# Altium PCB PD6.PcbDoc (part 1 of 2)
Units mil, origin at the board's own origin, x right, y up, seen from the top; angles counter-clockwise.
Board outline 8543.31 x 5314.96 mil, 4 copper layers (Top Layer, VBAT Plane, GND Plane, Bottom Layer), stack 62.8 mil thick; 258 components, 142 nets, 690 pads, 87 vias.
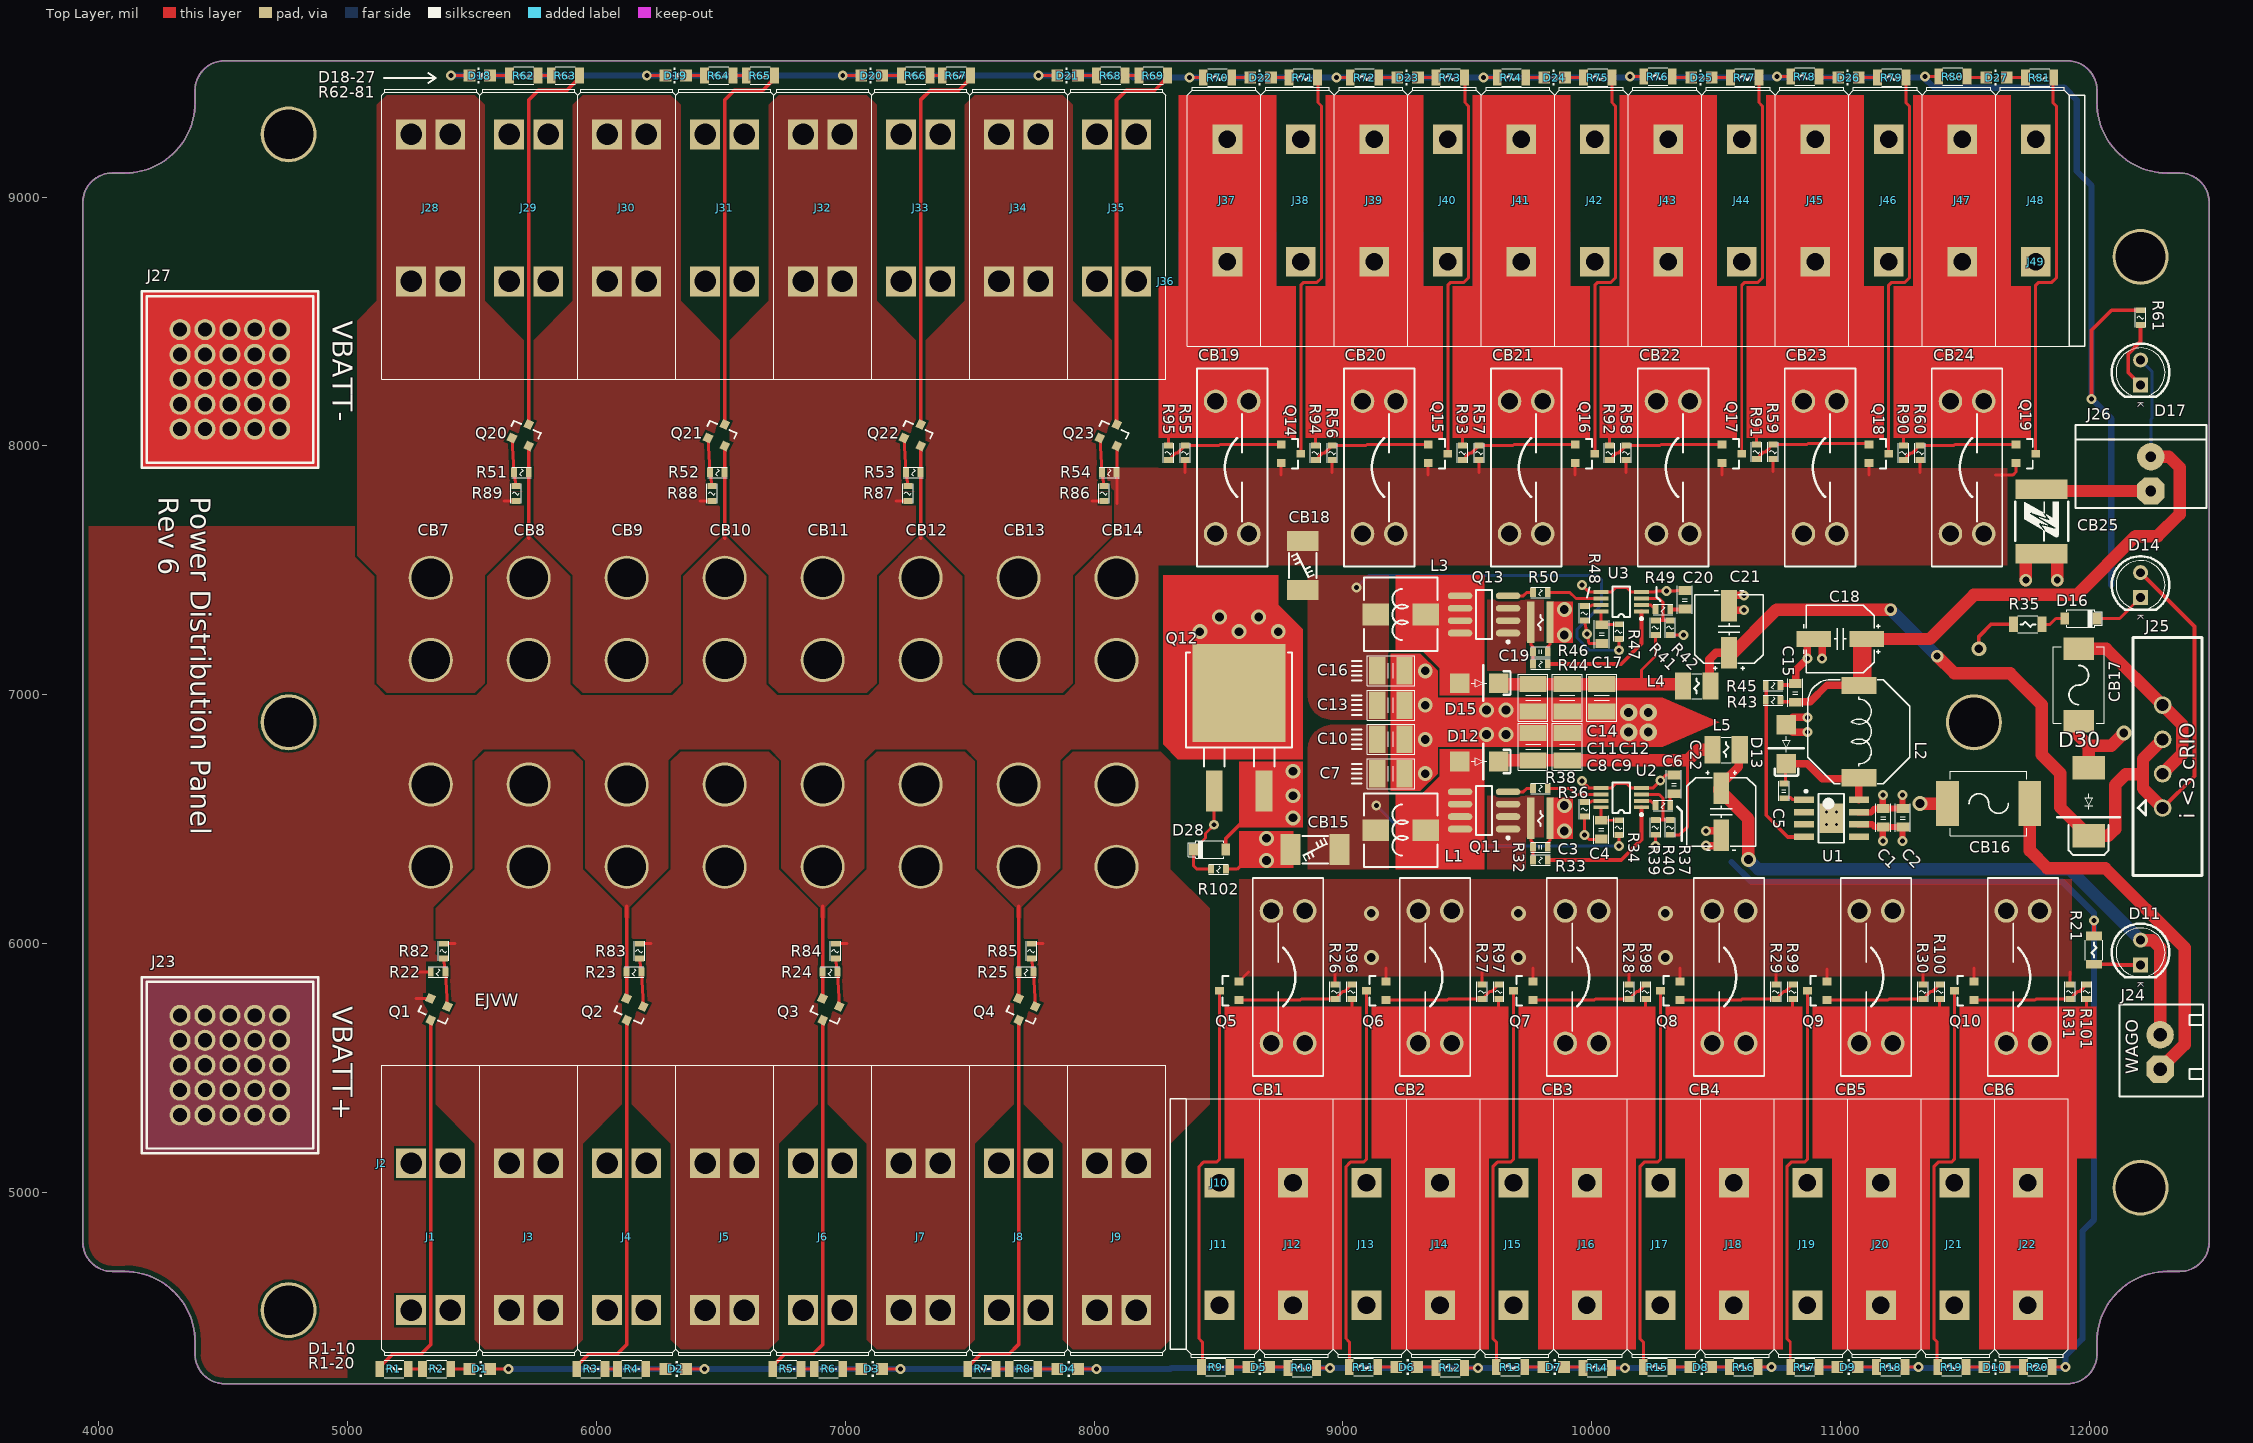
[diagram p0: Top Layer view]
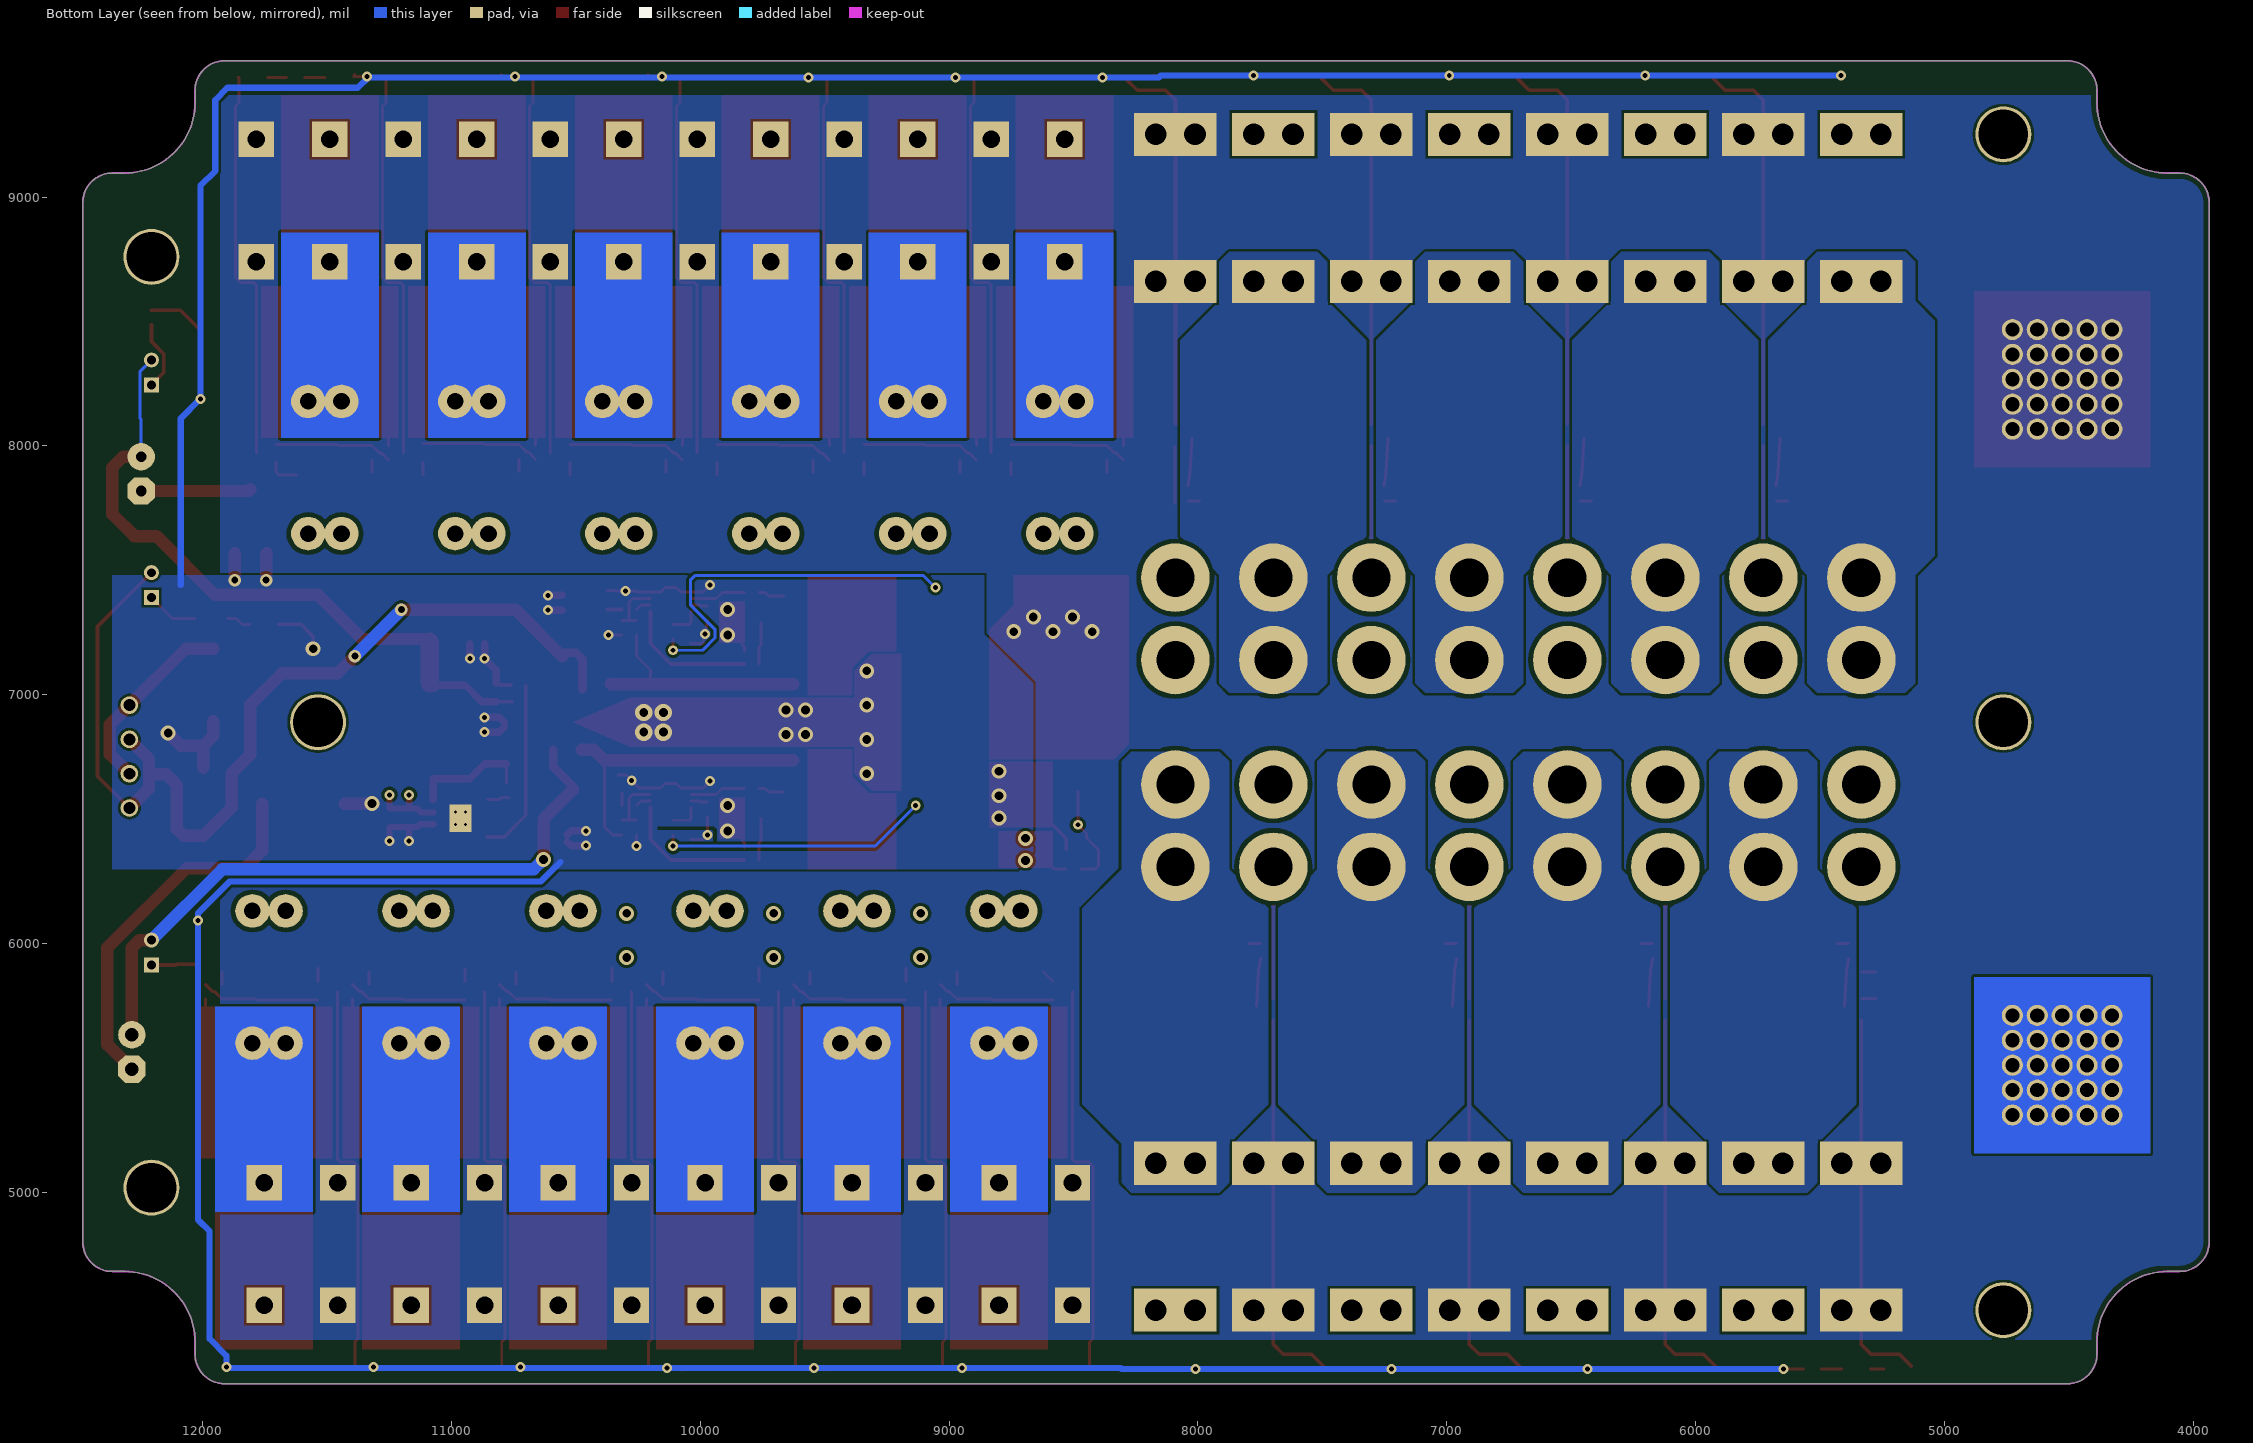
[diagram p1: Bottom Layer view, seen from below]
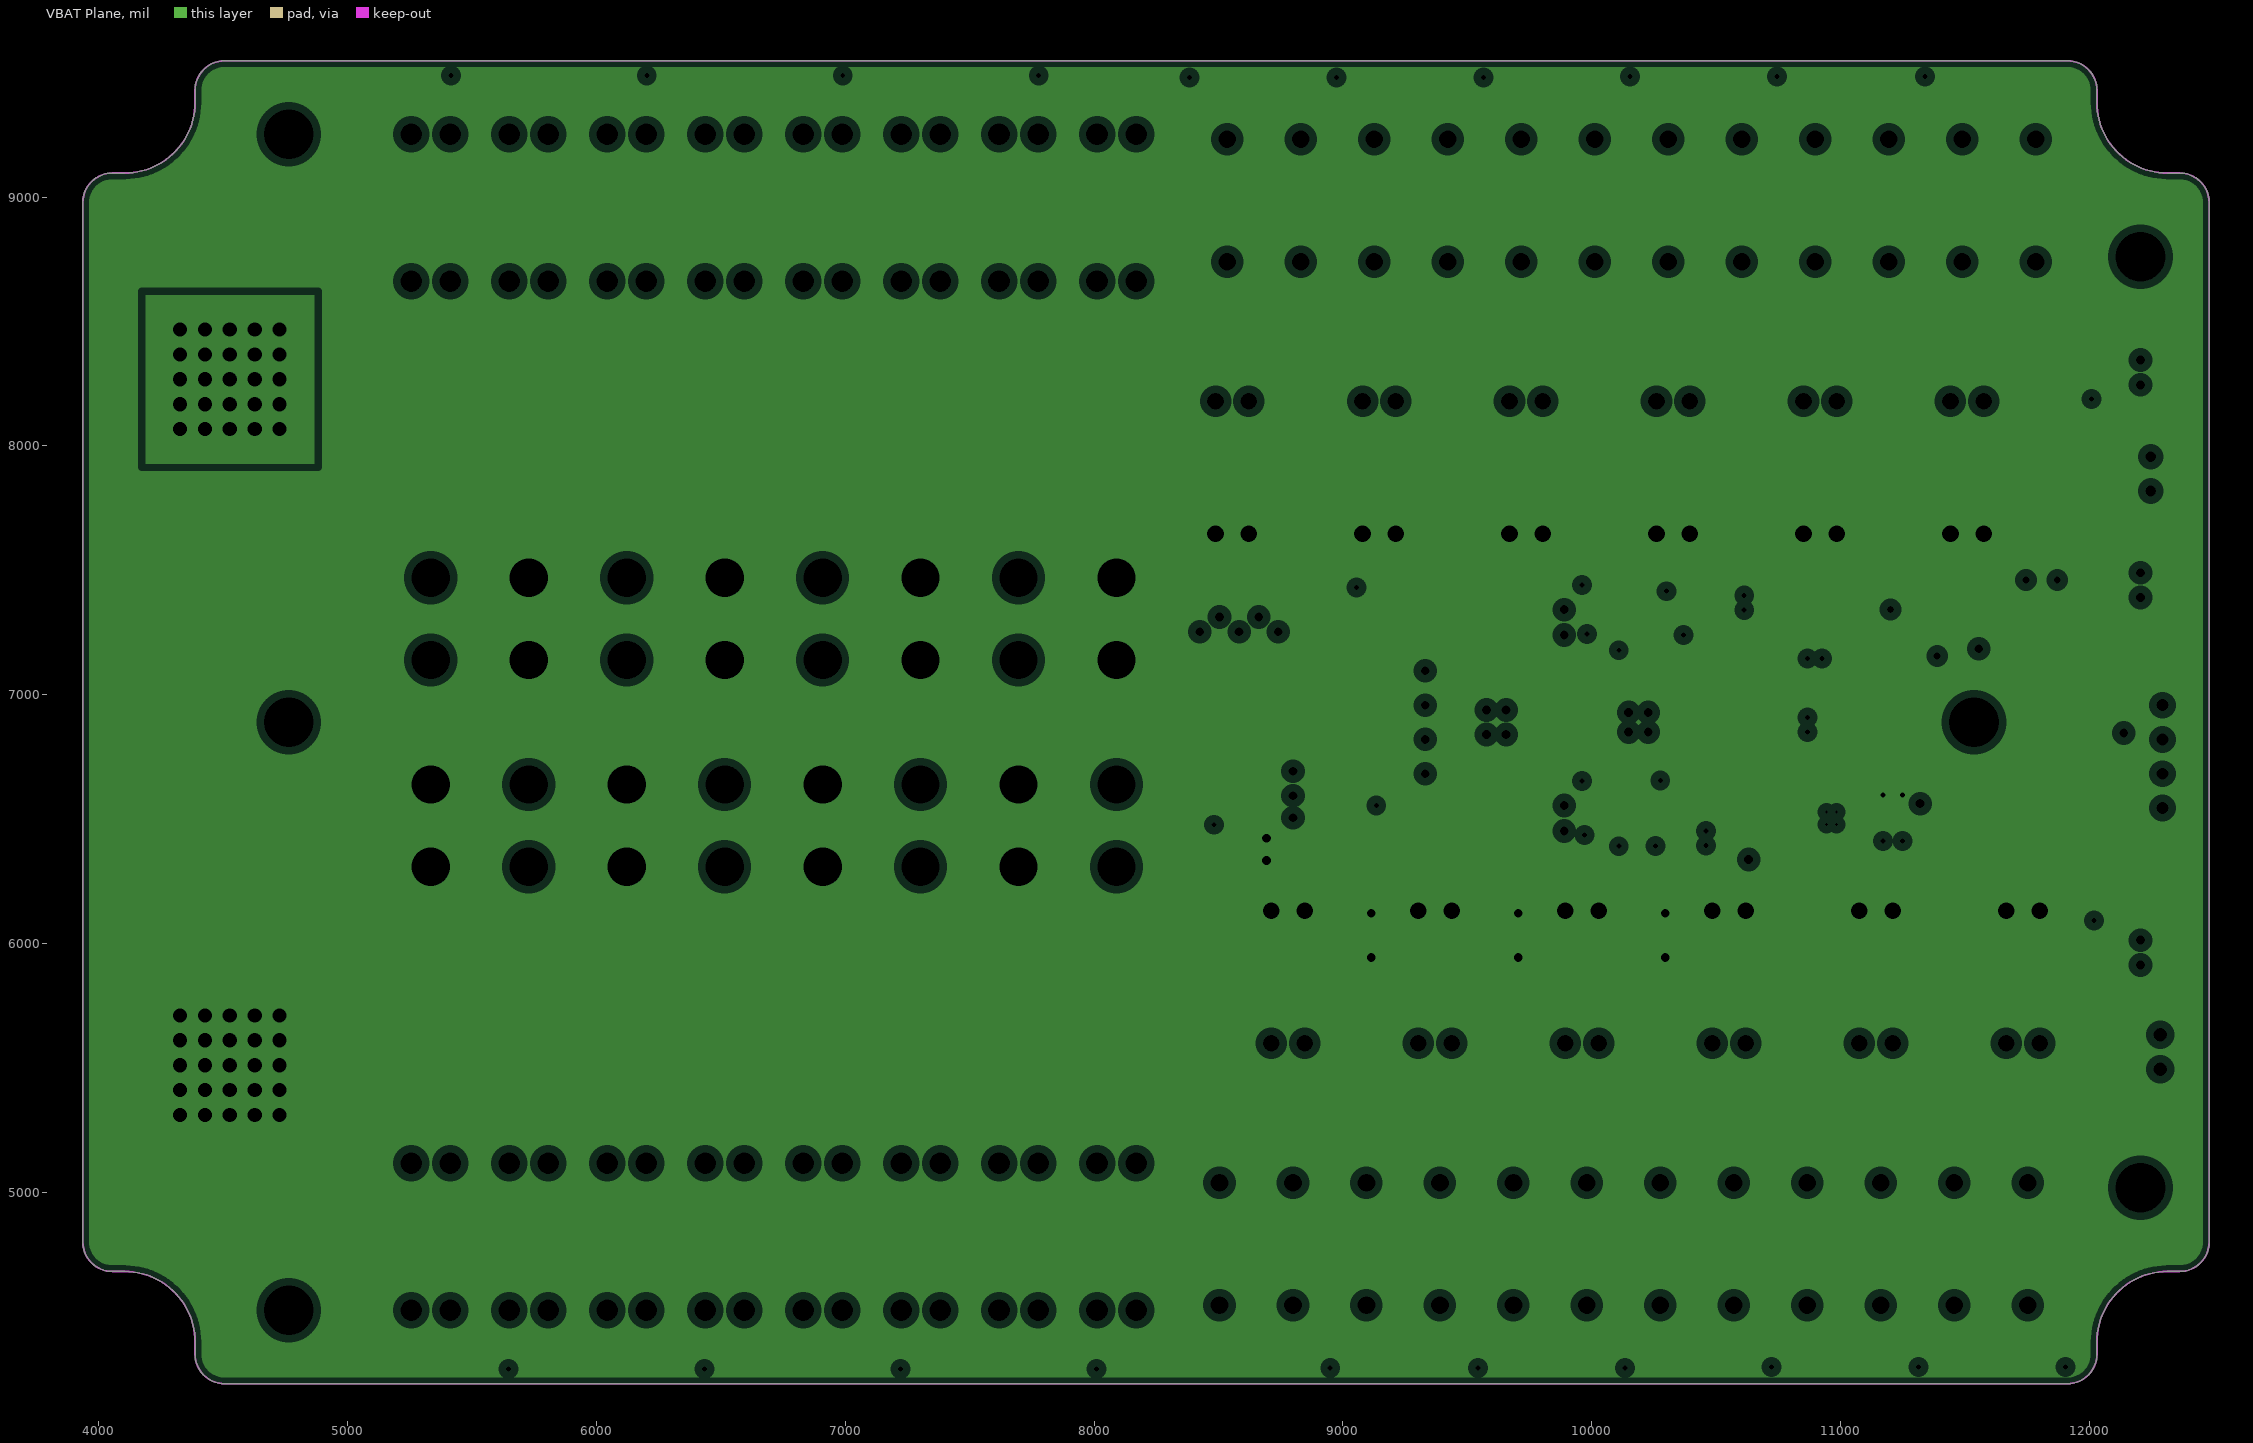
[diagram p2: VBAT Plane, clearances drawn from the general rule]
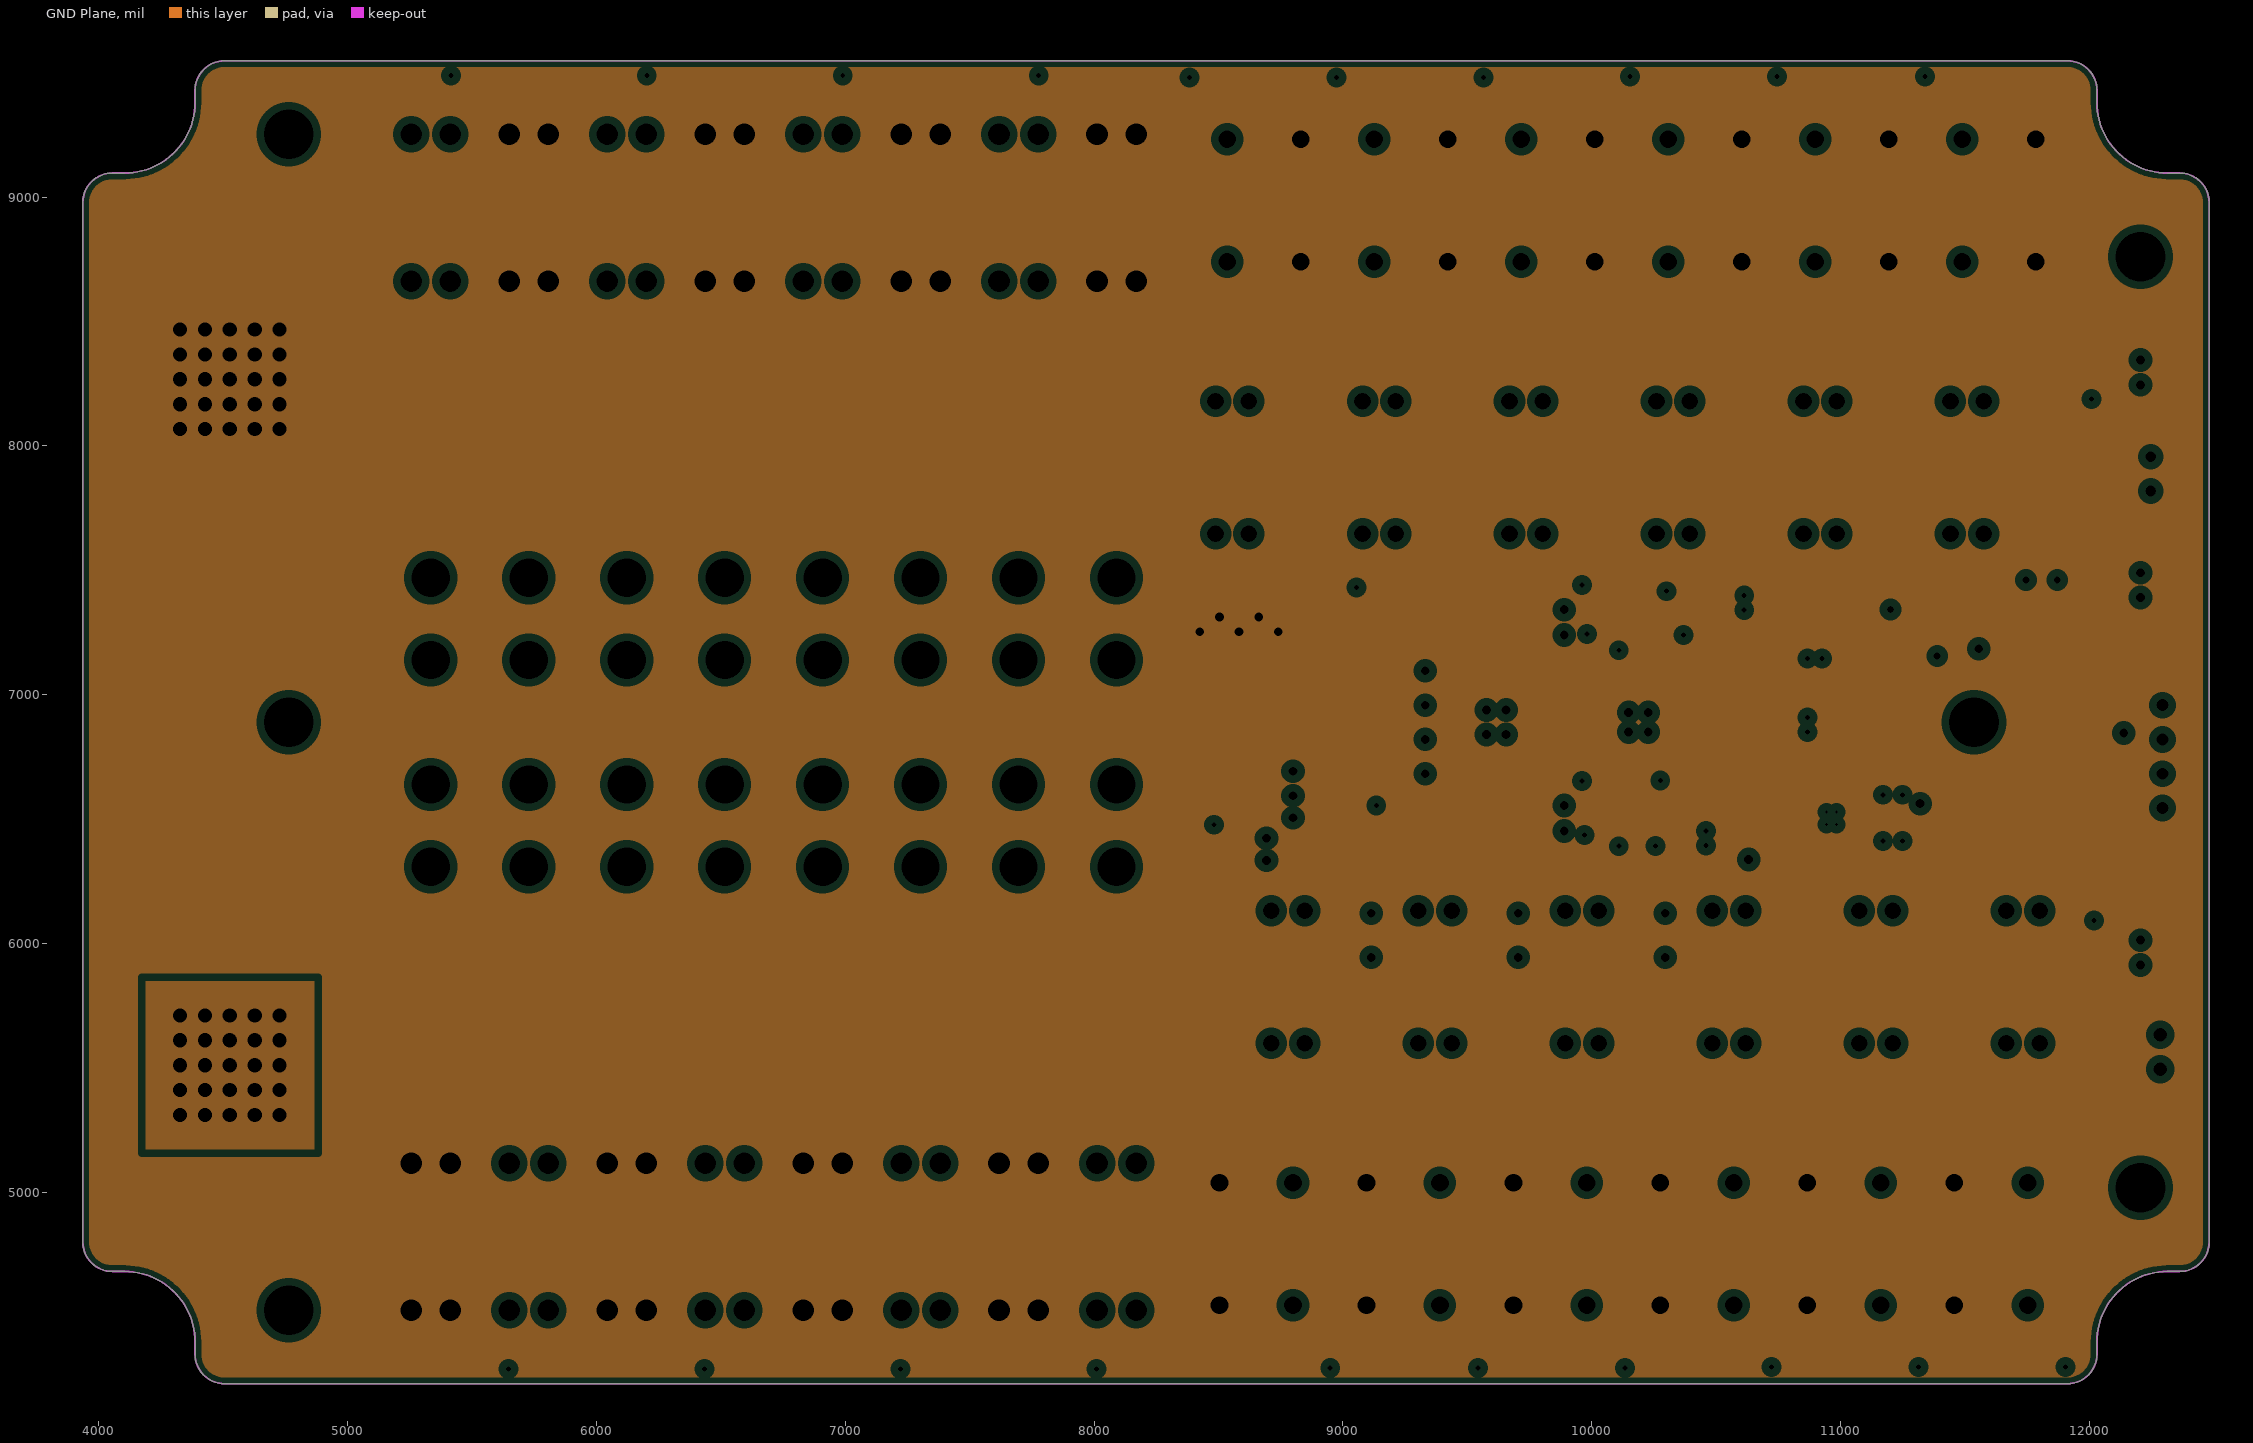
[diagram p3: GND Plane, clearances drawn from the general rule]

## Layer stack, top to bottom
Top Layer: signal copper 2.4
Dielectric: prepreg 10, FR-4, Dk 4.8
VBAT Plane: plane copper 5, net (Multiple Nets)
Dielectric: core 28, FR-4, Dk 4.8
GND Plane: plane copper 5, net (Multiple Nets)
Dielectric: prepreg 10, FR-4, Dk 4.8
Bottom Layer: signal copper 2.4

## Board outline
4055.12,4683.07 4104.33,4683.07 cw(c4104.33,4399.61) 4387.8,4399.61 4387.8,4350.39 ccw(c4505.91,4350.39) 4505.91,4232.28 11911.42,4232.28 ccw(c11911.42,4350.39) 12029.53,4350.39 12029.53,4399.61 cw(c12312.99,4399.61) 12312.99,4683.07 12362.2,4683.07 ccw(c12362.2,4801.18) 12480.31,4801.18 12480.31,8978.35 ccw(c12362.2,8978.35) 12362.2,9096.46 12312.99,9096.46 cw(c12312.99,9379.92) 12029.53,9379.92 12029.53,9429.13 ccw(c11911.42,9429.13) 11911.42,9547.24 4505.91,9547.24 ccw(c4505.91,9429.13) 4387.8,9429.13 4387.8,9379.92 cw(c4104.33,9379.92) 4104.33,9096.46 4055.12,9096.46 ccw(c4055.12,8978.35) 3937.01,8978.35 3937.01,4801.18 ccw(c4055.12,4801.18)

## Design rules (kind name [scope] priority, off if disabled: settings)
Clearance "CLR Inner Planes" [OnLayer('GND Plane') or OnLayer('VBAT Plane')] p1: gap=30
Clearance Clearance_Breakers [(HasFootprint('KEYSTONE 3555-2') OR HasFootprint('KEYSTONE 3557-2'))] p2: gap=18
Clearance CLR_Board_Edge [(InPolygon) vs OnLayer('Keep-Out Layer')] p3: gap=20
Clearance Clearance_PolyPoly [(InPolygon) vs (InPolygon or IsPad or IsFill)] p4: gap=10
Clearance CLR_Poly [(InPolygon)] p5: gap=12
Clearance [All] p6: gap=9.02
ComponentClearance "CC Wago236" [(HasFootprint('WAGO 236-74X') OR HasFootprint('WAGO 236-75X'))] p1 off: gap=-39.37 collisioncheckmode=3 verticalgap=0 showdistances=FALSE
ComponentClearance "ComponentClearance_WAGO Small" [(HasFootprint('WAGO 745-83X') OR HasFootprint('WAGO 745-83X Red') OR HasFootprint('WAGO 745-300')) vs (HasFootprint('WAGO 745-83X') OR HasFootprint('WAGO 745-83X Red') OR HasFootprint('WAGO 745-300'))] p2 off: gap=-3937.01 collisioncheckmode=3 verticalgap=0 showdistances=FALSE
ComponentClearance ComponentClearance_WAGOs [(HasFootprint('WAGO 745-85X') OR HasFootprint('WAGO 745-85X Red') OR HasFootprint('WAGO 745-500')) vs (HasFootprint('WAGO 745-85X') OR HasFootprint('WAGO 745-85X Red') OR HasFootprint('WAGO 745-500'))] p3 off: gap=-7874.02 collisioncheckmode=3 verticalgap=0 showdistances=FALSE
ComponentClearance [All] p4 off: gap=10 collisioncheckmode=3 verticalgap=10 showdistances=FALSE
Height Height_Bottom [OnLayer('Bottom Layer')] p1: minheight=0 maxheight=137.8 prefheight=39.37
Height [All] p2: minheight=0 maxheight=2500 prefheight=500
HoleSize [All] p1: absolutevalues=TRUE maxlimit=500 minlimit=10 maxpercent=80.000 minpercent=20.000
MinimumAnnularRing [All] p1: minimumring=10
PlaneClearance [All] p1: clearance=30
PlaneConnect PC_PowerSO8 [(HasFootprint('TPS543X'))] p1: planeconnectstyle=Direct reliefexpansion=20 reliefentries=4 reliefconductorwidth=10 reliefairgap=10
PlaneConnect PC_Wurth [(HasFootprint('WURTH 7460719'))] p2: planeconnectstyle=Direct reliefexpansion=20 reliefentries=4 reliefconductorwidth=10 reliefairgap=10
PlaneConnect "PC Wagos" [(HasFootprint('WAGO 745-83X') OR HasFootprint('WAGO 745-85X'))] p3: planeconnectstyle=Direct reliefexpansion=20 reliefentries=4 reliefconductorwidth=40 reliefairgap=25
PlaneConnect PC_Breakers [(HasFootprint('KEYSTONE 3555-2') OR HasFootprint('KEYSTONE 3557-2'))] p4: planeconnectstyle=Direct reliefexpansion=20 reliefentries=4 reliefconductorwidth=60 reliefairgap=20
PlaneConnect PC_Honkin [(InComponent('J1') OR InComponent('J2'))] p5: planeconnectstyle=Direct reliefexpansion=20 reliefentries=2 reliefconductorwidth=10 reliefairgap=10
PlaneConnect PC_Vias [IsVia] p6: planeconnectstyle=Direct reliefexpansion=20 reliefentries=4 reliefconductorwidth=10 reliefairgap=10
PlaneConnect [All] p7: planeconnectstyle=Direct reliefexpansion=30 reliefentries=4 reliefconductorwidth=30 reliefairgap=20
PolygonConnect "PGC Wago" [(HasFootprint('WAGO 745-83X') OR HasFootprint('WAGO 745-85X'))] p1: connectstyle=Direct reliefconductorwidth=45 reliefentries=4 polygonreliefangle="90 Angle"
PolygonConnect PGC_Breakers [HasFootprint('KEYSTONE 3555-2') OR HasFootprint('KEYSTONE 3557-2')] p2: connectstyle=Direct reliefconductorwidth=50 reliefentries=4 polygonreliefangle="45 Angle"
PolygonConnect PGC_Vias [(IsVia)] p3: connectstyle=Direct reliefconductorwidth=10 reliefentries=4 polygonreliefangle="90 Angle"
PolygonConnect PGC_VBAT_HP [All vs IsNamedPolygon('Top Layer-VBAT HP') or IsNamedPolygon('Bottom Layer-GND HP')] p4: connectstyle=Direct reliefconductorwidth=10 reliefentries=4 polygonreliefangle="45 Angle"
PolygonConnect [All] p5: connectstyle=Direct reliefconductorwidth=10 reliefentries=4 polygonreliefangle="90 Angle"
RoomDefinition "U_12V_2A Supply" [InComponentClass('U_12V_2A Supply')] p1: confinementstyle=ConfineIn formatcopy=TRUE lockcomponents=FALSE outline 8858.27,6299.21 10816.93,6299.21 10816.93,6889.76 8858.27,6889.76
RoomDefinition LPB2 [InComponentClass('LPB2')] p2: confinementstyle=ConfineIn formatcopy=TRUE lockcomponents=FALSE outline 8062.99,6889.76 12000,6889.76 12000,9645.67 8062.99,9645.67
RoomDefinition HPB1 [InComponentClass('HPB1')] p3: confinementstyle=ConfineIn formatcopy=TRUE lockcomponents=FALSE outline 8385.83,7677.17 5039.37,7677.17 5039.37,4133.86 8385.83,4133.86
RoomDefinition LPB1 [InComponentClass('LPB1')] p4: confinementstyle=ConfineIn formatcopy=TRUE lockcomponents=FALSE outline 12224.41,6889.76 8287.4,6889.76 8287.4,4133.86 12224.41,4133.86
RoomDefinition U1000 [InComponentClass('U1000')] p5: confinementstyle=ConfineIn formatcopy=TRUE lockcomponents=FALSE outline 8858.27,6889.76 10816.93,6889.76 10816.93,7480.31 8858.27,7480.31
RoomDefinition "U_5V_3A Supply" [InComponentClass('U_5V_3A Supply')] p6: confinementstyle=ConfineIn formatcopy=TRUE lockcomponents=FALSE outline 11299.21,6377.95 11299.21,7381.89 10669.29,7381.89 10669.29,6377.95
RoomDefinition HPB2 [InComponentClass('HPB2')] p7: confinementstyle=ConfineIn formatcopy=TRUE lockcomponents=FALSE outline 5039.37,6102.36 8385.83,6102.36 8385.83,9645.67 5039.37,9645.67
RoutingVias [All] p1: holewidth=30 width=50 viastyle="Through Hole" minholewidth=10 minwidth=30 maxholewidth=225 maxwidth=250
SolderMaskExpansion [All] p1: expansion=4
TestPointUsage [All] p1: valid=0 allowmultiple=FALSE
Testpoint [All] p1: side=15 testpointundercomponent=TRUE minsize=40 maxsize=100 preferedsize=60 minholesize=0 maxholesize=40 preferedholesize=32 testpointgrid=1 style=1021 order=0-112345678
Width Width_InnerPlanes [OnLayer('GND Plane') or OnLayer('VBAT Plane')] p1: maxlimit=100 minlimit=25 preferedwidth=30
Width [All] p2: maxlimit=500 minlimit=10 preferedwidth=12
14 further rules are at their usual default settings.

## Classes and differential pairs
component class "U_12V_2A Supply": C3 C4 C6 C7 C8 C9 C10 C22 D12 L1 L5 Q11 R32 R33 R34 R36 R37 R38 R39 R40 U2
component class "U_5V_3A Supply": C1 C2 C5 C15 C18 D13 L2 R43 R45 U1
component class PS1: CB15 CB16 CB17 CB18 CB25 D11 D14 D16 D17 D28 D30 J23 J24 J25 J26 J27 Q12 R21 R35 R61 R102
component class LPB2: CB19 CB20 CB21 CB22 CB23 CB24 D22 D23 D24 D25 D26 D27 J37 J38 J39 J40 J41 J42 J43 J44 J45 J46 J47 J48 J49 Q14 Q15 Q16 Q17 Q18 Q19 R55 R56 R57 R58 R59 R60 R70 R71 R72 R73 R74 R75 R76 R77 R78 R79 R80 R81 R90 R91 R92 R93 R94 R95
component class LPB1: CB1 CB2 CB3 CB4 CB5 CB6 D5 D6 D7 D8 D9 D10 J10 J11 J12 J13 J14 J15 J16 J17 J18 J19 J20 J21 J22 J50 Q5 Q6 Q7 Q8 Q9 Q10 R9 R10 R11 R12 R13 R14 R15 R16 R17 R18 R19 R20 R26 R27 R28 R29 R30 R31 R96 R97 R98 R99 R100 R101
component class HPB1: CB8 CB10 CB12 CB14 D1 D2 D3 D4 J1 J2 J3 J4 J5 J6 J7 J8 J9 Q1 Q2 Q3 Q4 R1 R2 R3 R4 R5 R6 R7 R8 R22 R23 R24 R25 R82 R83 R84 R85
channel class "PD - Low Power Bank": LPB1 LPB2
channel class "PD - High Power Bank": HPB1 HPB2
component class HPB2: CB7 CB9 CB11 CB13 D18 D19 D20 D21 J28 J29 J30 J31 J32 J33 J34 J35 J36 Q20 Q21 Q22 Q23 R51 R52 R53 R54 R62 R63 R64 R65 R66 R67 R68 R69 R86 R87 R88 R89
component class U1000: C11 C12 C13 C14 C16 C17 C19 C20 C21 D15 L3 L4 Q13 R41 R42 R44 R46 R47 R48 R49 R50 U3

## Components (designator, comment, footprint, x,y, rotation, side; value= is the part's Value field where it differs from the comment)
C1 "4.7UF 0805 25V X5R" C0805_C 11171.26,6505.91 r90 top (schematic designator C8)
C2 "4.7UF 0805 25V X5R" C0805_C 11250,6505.91 r90 top (schematic designator C9)
C3 "0.01uF 0603" C0603_C 9793.31,6387.8 r180 top (schematic designator C15)
C4 "0.1uF 0805 Bypass" C0805_C 10037.4,6458.66 r90 top (schematic designator C13)
C5 "0.01uF 0603" C0603_C 10771.65,6614.17 r90 top (schematic designator C10)
C6 "0.1uF 0805 Bypass" C0805_C 10330,6640 r270 top (schematic designator C14)
C7 "22uF 1210 High I_RMS" C1210_C 9192.91,6683.07 r180 top (schematic designator C16)
C8 "22uF 1210 High I_RMS" C1210_C 9763.78,6791.34 r270 top (schematic designator C18)
C9 "22uF 1210 High I_RMS" C1210_C 9901.57,6791.34 r270 top (schematic designator C17)
C10 "22uF 1210 High I_RMS" C1210_C 9192.91,6820.87 r180 top (schematic designator C19)
C11 "4.7uF 1210 High I_RMS" C1210_C 9901.57,6988.19 r90 top (schematic designator C6)
C12 "4.7uF 1210 High I_RMS" C1210_C 10039.37,6988.19 r90 top (schematic designator C5)
C13 "22uF 1210 High I_RMS" C1210_C 9192.91,6958.66 r180 top (schematic designator C4)
C14 "4.7uF 1210 High I_RMS" C1210_C 9763.78,6988.19 r90 top (schematic designator C7)
C15 "0.1uF 0805 Bypass" C0805_C 10816.93,7007.87 r270 top (schematic designator C11)
C16 "22uF 1210 High I_RMS" C1210_C 9192.91,7096.46 r180 top (schematic designator C20)
C17 "0.1uF 0805 Bypass" C0805_C 10039.37,7244.09 r90 top (schematic designator C1)
C18 "330µF SMT - Chemi-Con" "SMT-CAN NIPPON F80" 10998.03,7224.41 r270 top (schematic designator C12)
C19 "0.01uF 0603" C0603_C 9793.31,7173.23 r180 top (schematic designator C3)
C20 "0.1uF 0805 Bypass" C0805_C 10374.02,7381.89 r270 top (schematic designator C2)
C21 "100µF SMT - Panasonic" "SMT-CAN Panasonic D8" 10551.18,7263.78 r180 top
C22 "100µF SMT - Panasonic" "SMT-CAN Panasonic D8" 10520,6530 r0 top
CB1 "20/30 A Breaker Clip" "KEYSTONE 3557-2" 8779.53,5866.14 r270 top (schematic designator CB6)
CB2 "20/30 A Breaker Clip" "KEYSTONE 3557-2" 9370.08,5866.14 r270 top (schematic designator CB7)
CB3 "20/30 A Breaker Clip" "KEYSTONE 3557-2" 9960.63,5866.14 r270 top (schematic designator CB8)
CB4 "20/30 A Breaker Clip" "KEYSTONE 3557-2" 10551.18,5866.14 r270 top (schematic designator CB9)
CB5 "20/30 A Breaker Clip" "KEYSTONE 3557-2" 11141.73,5866.14 r270 top (schematic designator CB10)
CB6 "20/30 A Breaker Clip" "KEYSTONE 3557-2" 11732.28,5866.14 r270 top (schematic designator CB11)
CB7 "40 A Breaker Clip" "KEYSTONE 3555-2" 5334.65,6889.76 r90 top (schematic designator CB5)
CB8 "40 A Breaker Clip" "KEYSTONE 3555-2" 5728.35,6889.76 r270 top (schematic designator CB2)
CB9 "40 A Breaker Clip" "KEYSTONE 3555-2" 6122.05,6889.76 r90 top (schematic designator CB4)
CB10 "40 A Breaker Clip" "KEYSTONE 3555-2" 6515.75,6889.76 r270 top (schematic designator CB3)
CB11 "40 A Breaker Clip" "KEYSTONE 3555-2" 6909.45,6889.76 r90 top (schematic designator CB3)
CB12 "40 A Breaker Clip" "KEYSTONE 3555-2" 7303.15,6889.76 r270 top (schematic designator CB4)
CB13 "40 A Breaker Clip" "KEYSTONE 3555-2" 7696.85,6889.76 r90 top (schematic designator CB2)
CB14 "40 A Breaker Clip" "KEYSTONE 3555-2" 8090.55,6889.76 r270 top (schematic designator CB5)
CB15 "15A 125V" "FUSE2410 - BEL" 8887.8,6377.95 r180 top (schematic designator CB14)
CB16 "2 A Hold, 4 A Trip" PTC-MF-SM-Large 11594.49,6562.99 r0 top (schematic designator CB13)
CB17 "1.1 A Hold, 2.2 A Trip" PTC-MF-SM-Small 11956.69,7039.37 r90 top (schematic designator CB12)
CB18 "15A 125V" "FUSE2410 - BEL" 8838.58,7519.69 r90 top (schematic designator CB1)
CB19 "20/30 A Breaker Clip" "KEYSTONE 3557-2" 8555.12,7913.39 r90 top (schematic designator CB11)
CB20 "20/30 A Breaker Clip" "KEYSTONE 3557-2" 9145.67,7913.39 r90 top (schematic designator CB10)
CB21 "20/30 A Breaker Clip" "KEYSTONE 3557-2" 9736.22,7913.39 r90 top (schematic designator CB9)
CB22 "20/30 A Breaker Clip" "KEYSTONE 3557-2" 10326.77,7913.39 r90 top (schematic designator CB8)
CB23 "20/30 A Breaker Clip" "KEYSTONE 3557-2" 10917.32,7913.39 r90 top (schematic designator CB7)
CB24 "20/30 A Breaker Clip" "KEYSTONE 3557-2" 11507.87,7913.39 r90 top (schematic designator CB6)
CB25 "3 A Hold, 5 A Trip" 2920L 11807.09,7696.85 r90 top (schematic designator CB15)
D1 "Red 0805 2.0V 20mA 104mCd" "LED_0805 0.8 Red" 5531.5,4291.34 r0 top (schematic designator D2)
D2 "Red 0805 2.0V 20mA 104mCd" "LED_0805 0.8 Red" 6318.9,4291.34 r0 top (schematic designator D3)
D3 "Red 0805 2.0V 20mA 104mCd" "LED_0805 0.8 Red" 7106.3,4291.34 r0 top (schematic designator D4)
D4 "Red 0805 2.0V 20mA 104mCd" "LED_0805 0.8 Red" 7893.7,4291.34 r0 top (schematic designator D5)
D5 "Red 0805 2.0V 20mA 104mCd" "LED_0805 0.8 Red" 8661.42,4299.21 r0 top (schematic designator D6)
D6 "Red 0805 2.0V 20mA 104mCd" "LED_0805 0.8 Red" 9255.91,4299.21 r0 top (schematic designator D7)
D7 "Red 0805 2.0V 20mA 104mCd" "LED_0805 0.8 Red" 9846.46,4299.21 r0 top (schematic designator D8)
D8 "Red 0805 2.0V 20mA 104mCd" "LED_0805 0.8 Red" 10437.01,4299.21 r0 top (schematic designator D9)
D9 "Red 0805 2.0V 20mA 104mCd" "LED_0805 0.8 Red" 11027.56,4299.21 r0 top (schematic designator D10)
D10 "Red 0805 2.0V 20mA 104mCd" "LED_0805 0.8 Red" 11618.11,4299.21 r0 top (schematic designator D11)
D11 "Green" "T-1 3/4" 12204.72,5964.57 r270 top (schematic designator D17)
D12 "MBRA340T3G" SMA 9547.24,6732.28 r0 top (schematic designator D16)
D13 "MBRA340T3G" SMA 10781.5,6801.18 r270 top (schematic designator D12)
D14 "Green" "T-1 3/4" 12204.72,7440.94 r270 top
D15 "MBRA340T3G" SMA 9547.24,7047.24 r0 top (schematic designator D1)
D16 "MMSZ5242BT1G" SOD-123 11964.57,7307.09 r180 top (schematic designator D13)
D17 "Green" "T-1 3/4" 12204.72,8295.28 r270 top (schematic designator D15)
D18 "Red 0805 2.0V 20mA 104mCd" "LED_0805 0.8 Red" 5531.5,9488.19 r180 top (schematic designator D5)
D19 "Red 0805 2.0V 20mA 104mCd" "LED_0805 0.8 Red" 6318.9,9488.19 r180 top (schematic designator D4)
D20 "Red 0805 2.0V 20mA 104mCd" "LED_0805 0.8 Red" 7106.3,9488.19 r180 top (schematic designator D3)
D21 "Red 0805 2.0V 20mA 104mCd" "LED_0805 0.8 Red" 7893.7,9488.19 r180 top (schematic designator D2)
D22 "Red 0805 2.0V 20mA 104mCd" "LED_0805 0.8 Red" 8669.29,9480.32 r180 top (schematic designator D11)
D23 "Red 0805 2.0V 20mA 104mCd" "LED_0805 0.8 Red" 9259.84,9480.32 r180 top (schematic designator D10)
D24 "Red 0805 2.0V 20mA 104mCd" "LED_0805 0.8 Red" 9850.39,9480.31 r180 top (schematic designator D9)
D25 "Red 0805 2.0V 20mA 104mCd" "LED_0805 0.8 Red" 10440.94,9480.32 r180 top (schematic designator D8)
D26 "Red 0805 2.0V 20mA 104mCd" "LED_0805 0.8 Red" 11031.5,9480.31 r180 top (schematic designator D7)
D27 "Red 0805 2.0V 20mA 104mCd" "LED_0805 0.8 Red" 11625.98,9480.32 r180 top (schematic designator D6)
D28 "MMSZ5242BT1G" SOD-123 8464.57,6377.95 r0 top (schematic designator D18)
D30 "TVS Uni 26V 1500W" SMC 11996.06,6570.87 r270 top (schematic designator D20)
J1 "745-851" "WAGO 745-85X" 5807.09,5118.11 r180 top (schematic designator J4)
J2 "745-851" "WAGO 745-500" 5137.8,5118.11 r180 top (schematic designator J3)
J3 "745-85X Red" "WAGO 745-85X RED" 6200.79,5118.11 r180 top (schematic designator J5)
J4 "745-851" "WAGO 745-85X" 6594.49,5118.11 r180 top (schematic designator J6)
J5 "745-85X Red" "WAGO 745-85X RED" 6988.19,5118.11 r180 top (schematic designator J7)
J6 "745-851" "WAGO 745-85X" 7381.89,5118.11 r180 top (schematic designator J8)
J7 "745-85X Red" "WAGO 745-85X RED" 7775.59,5118.11 r180 top (schematic designator J9)
J8 "745-851" "WAGO 745-85X" 8169.29,5118.11 r180 top (schematic designator J10)
J9 "745-85X Red" "WAGO 745-85X RED" 8562.99,5118.11 r180 top (schematic designator J11)
J10 "745-300" "WAGO 745-300" 8503.94,5039.37 r180 top (schematic designator J12)
J11 "745-831" "WAGO 745-83X" 8799.21,5039.37 r180 top (schematic designator J13)
J12 "745-83X Red" "WAGO 745-83X Red" 9094.49,5039.37 r180 top (schematic designator J14)
J13 "745-831" "WAGO 745-83X" 9389.76,5039.37 r180 top (schematic designator J15)
J14 "745-83X Red" "WAGO 745-83X Red" 9685.04,5039.37 r180 top (schematic designator J16)
J15 "745-831" "WAGO 745-83X" 9980.32,5039.37 r180 top (schematic designator J17)
J16 "745-83X Red" "WAGO 745-83X Red" 10275.59,5039.37 r180 top (schematic designator J18)
J17 "745-831" "WAGO 745-83X" 10570.87,5039.37 r180 top (schematic designator J19)
J18 "745-83X Red" "WAGO 745-83X Red" 10866.14,5039.37 r180 top (schematic designator J20)
J19 "745-831" "WAGO 745-83X" 11161.42,5039.37 r180 top (schematic designator J21)
J20 "745-83X Red" "WAGO 745-83X Red" 11456.69,5039.37 r180 top (schematic designator J22)
J21 "745-831" "WAGO 745-83X" 11751.97,5039.37 r180 top (schematic designator J23)
J22 "745-83X Red" "WAGO 745-83X Red" 12047.24,5039.37 r180 top (schematic designator J24)
J23 "M6 Shank, Pressfit" "Wurth 7461098" 4527.56,5511.81 r0 top (schematic designator J1)
J24 "3.5mm Mini Header" "WAGO 734-132" 12283.46,5496.06 r90 top (schematic designator J27)
J25 "Sauro CTM040V8" "SAURO CTM040V8" 12293.31,6751.97 r90 top
J26 "3.5mm Mini Header" "WAGO 739-302" 12246.06,7818.9 r90 top
J27 "M6 Shank, Pressfit" "Wurth 7461098" 4527.56,8267.72 r0 top (schematic designator J2)
J28 "745-85X Red" "WAGO 745-85X RED" 4862.2,8661.42 r0 top (schematic designator J11)
J29 "745-851" "WAGO 745-85X" 5255.91,8661.42 r0 top (schematic designator J10)
J30 "745-85X Red" "WAGO 745-85X RED" 5649.61,8661.42 r0 top (schematic designator J9)
J31 "745-851" "WAGO 745-85X" 6043.31,8661.42 r0 top (schematic designator J8)
J32 "745-85X Red" "WAGO 745-85X RED" 6437.01,8661.42 r0 top (schematic designator J7)
J33 "745-851" "WAGO 745-85X" 6830.71,8661.42 r0 top (schematic designator J6)
J34 "745-85X Red" "WAGO 745-85X RED" 7224.41,8661.42 r0 top (schematic designator J5)
J35 "745-851" "WAGO 745-85X" 7618.11,8661.42 r0 top (schematic designator J4)
J36 "745-851" "WAGO 745-500" 8287.4,8661.42 r0 top (schematic designator J3)
J37 "745-83X Red" "WAGO 745-83X Red" 8240.16,8740.16 r0 top (schematic designator J24)
J38 "745-831" "WAGO 745-83X" 8535.43,8740.16 r0 top (schematic designator J23)
J39 "745-83X Red" "WAGO 745-83X Red" 8830.71,8740.16 r0 top (schematic designator J22)
J40 "745-831" "WAGO 745-83X" 9125.98,8740.16 r0 top (schematic designator J21)
J41 "745-83X Red" "WAGO 745-83X Red" 9421.26,8740.16 r0 top (schematic designator J20)
J42 "745-831" "WAGO 745-83X" 9716.54,8740.16 r0 top (schematic designator J19)
J43 "745-83X Red" "WAGO 745-83X Red" 10011.81,8740.16 r0 top (schematic designator J18)
J44 "745-831" "WAGO 745-83X" 10307.09,8740.16 r0 top (schematic designator J17)
J45 "745-83X Red" "WAGO 745-83X Red" 10602.36,8740.16 r0 top (schematic designator J16)
J46 "745-831" "WAGO 745-83X" 10897.64,8740.16 r0 top (schematic designator J15)
J47 "745-83X Red" "WAGO 745-83X Red" 11192.91,8740.16 r0 top (schematic designator J14)
J48 "745-831" "WAGO 745-83X" 11488.19,8740.16 r0 top (schematic designator J13)
J49 "745-300" "WAGO 745-300" 11783.46,8740.16 r0 top (schematic designator J12)
L1 "4.7 µH 6 A" "WURTH WE-HC 744314X" 9232.28,6456.69 r270 top (schematic designator L3)
L2 "18 µH 3.35A ±20% SMD" "COILCRAFT MSS1038" 11072.83,6852.36 r180 top
L3 "4.7 µH 6 A" "WURTH WE-HC 744314X" 9232.28,7322.83 r270 top (schematic designator L1)
L4 "0 ohm 1210" R1210_C 10421.26,7035.43 r0 top
L5 "0 ohm 1210" R1210_C 10539.37,6779.53 r0 top
Q1 "FDV302P" "SOT-23 FET" 5351.28,5728.35 r245 top (schematic designator Q2)
Q2 "FDV302P" "SOT-23 FET" 6138.69,5728.35 r245 top (schematic designator Q3)
Q3 "FDV302P" "SOT-23 FET" 6926.09,5728.35 r245 top (schematic designator Q4)
Q4 "FDV302P" "SOT-23 FET" 7713.49,5728.35 r245 top (schematic designator Q5)
Q5 "FDV302P" "SOT-23 FET" 8543.31,5811.02 r180 top (schematic designator Q6)
Q6 "FDV302P" "SOT-23 FET" 9133.86,5811.02 r180 top (schematic designator Q7)
Q7 "FDV302P" "SOT-23 FET" 9724.41,5811.02 r180 top (schematic designator Q8)
Q8 "FDV302P" "SOT-23 FET" 10314.96,5811.02 r180 top (schematic designator Q9)
Q9 "FDV302P" "SOT-23 FET" 10905.51,5811.02 r180 top (schematic designator Q10)
Q10 "FDV302P" "SOT-23 FET" 11496.06,5811.02 r180 top (schematic designator Q11)
Q11 "IRF8721PbF" "SO-8_M FET" 9566.93,6535.43 r180 top (schematic designator Q12)
Q12 "FQB33N10TM" TO-263AB/D2PAK 8582.68,6614.17 r0 top (schematic designator Q13)
Q13 "FDS8447" "SO-8_M FET" 9566.93,7322.83 r180 top (schematic designator Q1)
Q14 "FDV302P" "SOT-23 FET" 8791.34,7968.5 r0 top (schematic designator Q11)
Q15 "FDV302P" "SOT-23 FET" 9381.89,7968.5 r0 top (schematic designator Q10)
Q16 "FDV302P" "SOT-23 FET" 9972.44,7968.5 r0 top (schematic designator Q9)
Q17 "FDV302P" "SOT-23 FET" 10562.99,7968.5 r0 top (schematic designator Q8)
Q18 "FDV302P" "SOT-23 FET" 11153.54,7968.5 r0 top (schematic designator Q7)
Q19 "FDV302P" "SOT-23 FET" 11744.09,7968.5 r0 top (schematic designator Q6)
Q20 "FDV302P" "SOT-23 FET" 5711.71,8051.18 r65 top (schematic designator Q5)
Q21 "FDV302P" "SOT-23 FET" 6499.11,8051.18 r65 top (schematic designator Q4)
Q22 "FDV302P" "SOT-23 FET" 7286.51,8051.18 r65 top (schematic designator Q3)
Q23 "FDV302P" "SOT-23 FET" 8073.91,8051.18 r65 top (schematic designator Q2)
R1 "240 ohm 1206 5%" R1206_C 5187.01,4291.34 r0 top (schematic designator R8)
R2 "270 ohm 1206 5%" R1206_C 5358.27,4291.34 r0 top (schematic designator R12)
R3 "240 ohm 1206 5%" R1206_C 5978.35,4291.34 r0 top (schematic designator R9)
R4 "270 ohm 1206 5%" R1206_C 6141.73,4291.34 r0 top (schematic designator R13)
R5 "240 ohm 1206 5%" R1206_C 6765.75,4291.34 r0 top (schematic designator R10)
R6 "270 ohm 1206 5%" R1206_C 6933.07,4291.34 r0 top (schematic designator R14)
R7 "240 ohm 1206 5%" R1206_C 7549.21,4291.34 r0 top (schematic designator R11)
R8 "270 ohm 1206 5%" R1206_C 7716.54,4291.34 r0 top (schematic designator R15)
R9 "240 ohm 1206 5%" R1206_C 8488.19,4299.21 r0 top (schematic designator R16)
R10 "270 ohm 1206 5%" R1206_C 8836.61,4295.28 r0 top (schematic designator R22)
R11 "240 ohm 1206 5%" R1206_C 9082.68,4299.21 r0 top (schematic designator R17)
R12 "270 ohm 1206 5%" R1206_C 9431.1,4295.28 r0 top (schematic designator R23)
R13 "240 ohm 1206 5%" R1206_C 9673.23,4299.21 r0 top (schematic designator R18)
R14 "270 ohm 1206 5%" R1206_C 10021.65,4295.28 r0 top (schematic designator R24)
R15 "240 ohm 1206 5%" R1206_C 10263.78,4299.21 r0 top (schematic designator R19)
R16 "270 ohm 1206 5%" R1206_C 10610.24,4299.21 r0 top (schematic designator R25)
R17 "240 ohm 1206 5%" R1206_C 10856.3,4299.21 r0 top (schematic designator R20)
R18 "270 ohm 1206 5%" R1206_C 11200.79,4299.21 r0 top (schematic designator R26)
R19 "240 ohm 1206 5%" R1206_C 11446.85,4299.21 r0 top (schematic designator R21)
R20 "270 ohm 1206 5%" R1206_C 11791.34,4299.21 r0 top (schematic designator R27)
R21 "510 ohm 1206 1%" R1206_C 12017.72,5974.41 r270 top (schematic designator R51)
R22 "100k ohm 0603 1%" R0603_C 5364.17,5885.83 r0 top (schematic designator R32)
R23 "100k ohm 0603 1%" R0603_C 6151.57,5885.83 r0 top (schematic designator R33)
R24 "100k ohm 0603 1%" R0603_C 6938.98,5885.83 r0 top (schematic designator R34)
R25 "100k ohm 0603 1%" R0603_C 7726.38,5885.83 r0 top (schematic designator R35)
R26 "100k ohm 0603 1%" R0603_C 8968.5,5807.09 r270 top (schematic designator R36)
R27 "100k ohm 0603 1%" R0603_C 9559.06,5807.09 r270 top (schematic designator R37)
R28 "100k ohm 0603 1%" R0603_C 10149.61,5807.09 r270 top (schematic designator R38)
R29 "100k ohm 0603 1%" R0603_C 10740.16,5807.09 r270 top (schematic designator R39)
R30 "100k ohm 0603 1%" R0603_C 11330.71,5807.09 r270 top (schematic designator R40)
R31 "100k ohm 0603 1%" R0603_C 11921.26,5807.09 r270 top (schematic designator R41)
R32 "15 milliohm RL3720 2% 1W" "RL3720 - SUSUMU" 9793.31,6503.94 r180 top (schematic designator R48)
R33 "604 ohm 0603 1%" R0603_C 9793.31,6336.61 r180 top (schematic designator R45)
R34 "20 ohm 0603 1%" R0603_C 10108.27,6466.54 r270 top (schematic designator R42)
R35 "510 ohm 1206 1%" R1206_C 11751.97,7283.46 r0 top (schematic designator R30)
R36 "24k ohm 0603 1%" R0603_C 9970.47,6540.35 r90 top (schematic designator R43)
R37 "1.0k ohm 0603 1%" R0603_C 10285.43,6555.12 r180 top (schematic designator R44)
R38 "0 ohm 0603" R0603_C 9793.31,6624.02 r180 top (schematic designator R50)
R39 "1.0k ohm 0603 1%" R0603_C 10255.75,6467.17 r90 top (schematic designator R47)
R40 "8.45k ohm 0603 1%" R0603_C 10314.8,6467.17 r270 top (schematic designator R46)
R41 "18k ohm 0603 1%" R0603_C 10255.91,7269.69 r270 top (schematic designator R5)
R42 "1.0k ohm 0603 1%" R0603_C 10314.96,7269.69 r90 top (schematic designator R6)
R43 "10k ohm 0603 1%" R0603_C 10728.35,6978.35 r0 top (schematic designator R28)
R44 "604 ohm 0603 1%" R0603_C 9793.31,7124.02 r180 top (schematic designator R4)
R45 "3.16k ohm 0603 1%" R0603_C 10728.35,7037.4 r180 top (schematic designator R29)
R46 "15 milliohm RL3720 2% 1W" "RL3720 - SUSUMU" 9793.31,7291.34 r180 top (schematic designator R7)
R47 "20 ohm 0603 1%" R0603_C 10108.27,7253.94 r90 top (schematic designator R1)
R48 "24k ohm 0603 1%" R0603_C 9970.47,7327.76 r90 top (schematic designator R2)
R49 "1.0k ohm 0603 1%" R0603_C 10285.43,7342.52 r180 top (schematic designator R3)
R50 "0 ohm 0603" R0603_C 9793.31,7411.42 r180 top (schematic designator R49)
R51 "100k ohm 0603 1%" R0603_C 5698.82,7893.7 r180 top (schematic designator R35)
R52 "100k ohm 0603 1%" R0603_C 6486.22,7893.7 r180 top (schematic designator R34)
R53 "100k ohm 0603 1%" R0603_C 7273.62,7893.7 r180 top (schematic designator R33)
R54 "100k ohm 0603 1%" R0603_C 8061.02,7893.7 r180 top (schematic designator R32)
R55 "100k ohm 0603 1%" R0603_C 8366.14,7972.44 r90 top (schematic designator R41)
R56 "100k ohm 0603 1%" R0603_C 8956.69,7972.44 r90 top (schematic designator R40)
R57 "100k ohm 0603 1%" R0603_C 9547.24,7972.44 r90 top (schematic designator R39)
R58 "100k ohm 0603 1%" R0603_C 10137.8,7972.44 r90 top (schematic designator R38)
R59 "100k ohm 0603 1%" R0603_C 10728.35,7976.38 r90 top (schematic designator R37)
R60 "100k ohm 0603 1%" R0603_C 11318.9,7972.44 r90 top (schematic designator R36)
R61 "130 ohm 0603 1%" R0603_C 12204.72,8515.75 r270 top (schematic designator R31)
R62 "270 ohm 1206 5%" R1206_C 5708.66,9488.19 r180 top (schematic designator R15)
R63 "240 ohm 1206 5%" R1206_C 5875.98,9488.19 r180 top (schematic designator R11)
R64 "270 ohm 1206 5%" R1206_C 6492.13,9488.19 r180 top (schematic designator R14)
R65 "240 ohm 1206 5%" R1206_C 6659.45,9488.19 r180 top (schematic designator R10)
R66 "270 ohm 1206 5%" R1206_C 7283.46,9488.19 r180 top (schematic designator R13)
R67 "240 ohm 1206 5%" R1206_C 7446.85,9488.19 r180 top (schematic designator R9)
R68 "270 ohm 1206 5%" R1206_C 8066.93,9488.19 r180 top (schematic designator R12)
R69 "240 ohm 1206 5%" R1206_C 8238.19,9488.19 r180 top (schematic designator R8)
R70 "270 ohm 1206 5%" R1206_C 8496.06,9480.31 r180 top (schematic designator R27)
R71 "240 ohm 1206 5%" R1206_C 8840.55,9480.31 r180 top (schematic designator R21)
R72 "270 ohm 1206 5%" R1206_C 9086.61,9480.31 r180 top (schematic designator R26)
R73 "240 ohm 1206 5%" R1206_C 9431.1,9480.31 r180 top (schematic designator R20)
R74 "270 ohm 1206 5%" R1206_C 9677.17,9480.32 r180 top (schematic designator R25)
R75 "240 ohm 1206 5%" R1206_C 10023.62,9480.31 r180 top (schematic designator R19)
R76 "270 ohm 1206 5%" R1206_C 10265.75,9484.25 r180 top (schematic designator R24)
R77 "240 ohm 1206 5%" R1206_C 10614.17,9480.32 r180 top (schematic designator R18)
R78 "270 ohm 1206 5%" R1206_C 10856.3,9484.25 r180 top (schematic designator R23)
R79 "240 ohm 1206 5%" R1206_C 11204.72,9480.31 r180 top (schematic designator R17)
R80 "270 ohm 1206 5%" R1206_C 11450.79,9484.25 r180 top (schematic designator R22)
R81 "240 ohm 1206 5%" R1206_C 11799.21,9480.32 r180 top (schematic designator R16)
R82 "200k ohm 0603 1%" R0603_C 5385.83,5970.47 r90 top (schematic designator R52)
R83 "200k ohm 0603 1%" R0603_C 6173.23,5970.47 r90 top (schematic designator R53)
R84 "200k ohm 0603 1%" R0603_C 6960.63,5970.47 r90 top (schematic designator R54)
R85 "200k ohm 0603 1%" R0603_C 7748.03,5970.47 r90 top (schematic designator R55)
R86 "200k ohm 0603 1%" R0603_C 8039.37,7809.06 r270 top (schematic designator R52)
R87 "200k ohm 0603 1%" R0603_C 7251.97,7809.06 r270 top (schematic designator R53)
R88 "200k ohm 0603 1%" R0603_C 6464.57,7809.06 r270 top (schematic designator R54)
R89 "200k ohm 0603 1%" R0603_C 5677.17,7809.06 r270 top (schematic designator R55)
R90 "200k ohm 0603 1%" R0603_C 11251.97,7972.44 r90 top (schematic designator R56)
R91 "200k ohm 0603 1%" R0603_C 10661.42,7976.38 r90 top (schematic designator R57)
R92 "200k ohm 0603 1%" R0603_C 10070.87,7972.44 r90 top (schematic designator R58)
R93 "200k ohm 0603 1%" R0603_C 9480.32,7972.44 r90 top (schematic designator R59)
R94 "200k ohm 0603 1%" R0603_C 8889.76,7972.44 r90 top (schematic designator R60)
R95 "200k ohm 0603 1%" R0603_C 8299.21,7972.44 r90 top (schematic designator R61)
R96 "200k ohm 0603 1%" R0603_C 9035.43,5807.09 r270 top (schematic designator R56)
R97 "200k ohm 0603 1%" R0603_C 9625.98,5807.09 r270 top (schematic designator R57)
R98 "200k ohm 0603 1%" R0603_C 10216.54,5807.09 r270 top (schematic designator R58)
R99 "200k ohm 0603 1%" R0603_C 10807.09,5807.09 r270 top (schematic designator R59)
R100 "200k ohm 0603 1%" R0603_C 11397.64,5807.09 r270 top (schematic designator R60)
R101 "200k ohm 0603 1%" R0603_C 11988.19,5807.09 r270 top (schematic designator R61)
R102 "100k ohm 0603 1%" R0603_C 8500,6299.21 r0 top (schematic designator R62)
U1 "Buck Converter" TPS543X 10962.83,6504.13 r0 top (schematic designator U2)
U2 "LM3478" MUA08A 10118.11,6586.61 r90 top (schematic designator U3)
U3 "LM3478" MUA08A 10118.11,7374.02 r90 top (schematic designator U1)

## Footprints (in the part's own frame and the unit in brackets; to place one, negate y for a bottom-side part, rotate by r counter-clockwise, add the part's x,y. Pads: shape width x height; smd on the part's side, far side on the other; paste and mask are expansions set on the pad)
2920L [mm] "POLYFUSE® Resettable PTCs  Surface Mount > 2920L Series"
  rect 2x5.3 smd: 1(-3.3,0) 2(3.3,0)
  silkscreen extent -2.03,-2.7 2,2.7, body extent -4,-2.7 4,2.7, height 0.4
C0603_C [mm]
  rect 0.6x0.9 smd: 1(-0.75,0) 2(0.75,0)
  silkscreen extent -1,-0.53 1,0.53, body extent -0.85,-0.45 0.85,0.45, height 0.9
C0805_C [mm]
  rect 0.9x1.3 smd: 1(-0.95,0) 2(0.95,0)
  silkscreen extent -1.43,-0.76 1.43,0.76, body extent -1.02,-0.64 1.02,0.64, height 1.25
C1210_C [mil]
  rect 65x110 smd: 1(-55,0) 2(55,0)
  silkscreen extent -95,-60 95,60, body extent -60,-50 60,50, height 16
"COILCRAFT MSS1038" [mm] "SMT Power Inductors"
  rect 3.56x1.78 smd: 1(0,4.7) 2(0,-4.7)
  silkscreen extent -5.2,-5.3 5.2,5.3, body extent -5,-5.1 5,5.1, height 3.8
"FUSE2410 - BEL" [mm] "bel SSQ Square Ceramic Surface Mount Quick Acting Fuse"
  rect 2x3.18 smd: 1(-2.5,0) 2(2.5,0)
  silkscreen extent -1.3,-1.4 1.3,1.4, body extent -3.05,-1.27 3.05,1.27, height 2.54
"KEYSTONE 3555-2" [mm]
  round 4.5 / inner round 7 / far side round 7 hole 3.9: 1(-14.75,0) 1(-6.35,0) 2(6.35,0) 2(14.75,0)
  body extent -15.96,-4.4 15.96,4.4, height 34
"KEYSTONE 3557-2" [mm]
  round 2.4 / inner round 3.4 / far side oval 3.4x3.5 hole 1.7: 1(-6.75,-1.7) 1(-6.75,1.7) 2(6.75,-1.7) 2(6.75,1.7)
  silkscreen extent -10.1,-3.6 10.1,3.6, body extent -9.9,-7.87 9.9,3.4, height 34.29
"LED_0805 0.8 Red" [mm] "0.8mm Red 0805 Led"
  rect 1.2x1.2 smd: A(-1.05,0) K(1.05,0)
  silkscreen extent -0.25,-0.82 0.28,0.83, body extent -1,-0.63 1,0.63, height 0.8
MUA08A [mm] "Shrink Small Outline; 8 Leads; Body Width 3 mm; Pitch 0.65 mm"
  rect 0.4x1.55 smd: 1(-0.975,-2.075) 2(-0.325,-2.075) 3(0.325,-2.075) 4(0.975,-2.075) 5(0.975,2.075) 6(0.325,2.075) 7(-0.325,2.075) 8(-0.975,2.075)
  silkscreen extent -1.85,-2.2 1.55,0.9, body extent -1.5,-1.5 1.5,1.5, height 1.09
PTC-MF-SM-Large [mm]
  rect 2.3x4.6 smd: 1(-4.2,0) 2(4.2,0)
  silkscreen extent -3.9,-3.3 3.9,3.3, body extent -4,-3.4 4,3.4, height 3.18
PTC-MF-SM-Small [mm]
  rect 2.3x3.1 smd: 1(-3.7,0) 2(3.7,0)
  silkscreen extent -3.9,-2.6 3.9,2.6, body extent -4,-2.7 4,2.7, height 3.18
R0603_C [mm]
  rect 0.6x0.9 smd: 1(-0.75,0) 2(0.75,0)
  silkscreen extent -1,-0.53 1,0.53, body extent -0.75,-0.4 0.75,0.4, height 0.4
R1206_C [mm]
  rect 0.9x1.6 smd: 1(-1.45,0) 2(1.45,0)
  silkscreen extent -1.02,-0.89 1.02,0.89, body extent -1.5,-0.9 1.5,0.9, height 0.4
R1210_C [mil]
  rect 65x110 smd: 1(-55,0) 2(55,0)
  silkscreen extent -20,-52 20,50, body extent -60,-50 60,50, height 16
"RL3720 - SUSUMU" [mm] "Susumu Long-side electrode Resistors"
  rect 0.75x4.2 smd: 1(-0.975,0) 2(0.975,0)
  silkscreen extent -0.25,-0.76 0.25,0.76, body extent -1,-1.88 1,1.88, height 0.55
"SAURO CTM040V8" [mm] "4 position vertical thru-hole connector with locking screw flanges, 3.5mm spacing"
  round 1.8 hole 1.2: 1(-5.25,0) 2(-1.75,0) 3(1.75,0) 4(5.25,0)
  silkscreen extent -12.15,-4 12.15,3, body extent -12.15,-4.8 12.15,6.3, height 18.1
SMA [mm] "DO-214-AC/SMA; 2 C-Bend Leads; Body 5.6 x 2.9 mm, inc. leads (LxW)"
  rect 2x2 smd: A(-2,0) K(2,0)
  silkscreen extent -0.8,-1.8 3.2,1.8, body extent -2.3,-1.5 2.3,1.5, height 2.4
SMC [mm] "DO-214-AB/SMC; 2 C-Bend Leads; Body 7.9 x 5.9 mm, inc. leads (LxW)"
  rect 2.4x3.3 smd: A(-3.475,0) K(3.475,0)
  silkscreen extent -0.8,-3.2 5.43,3.2, body extent -3.56,-3.17 3.56,3.18, height 2.64
"SMT-CAN NIPPON F80" [mm] "Nippon ChemiCon SMT-CAN type Capacitor, Size code F80"
  rect 1.6x3.5 smd: +(0,2.7) -(0,-2.7)
  silkscreen extent -3.45,-3.7 3.45,4.1, body extent -3.3,-3.3 3.3,3.3, height 7.7
"SMT-CAN Panasonic D8" [mm] "Panasonic SMT-CAN type Capacitor, Size code D8"
  rect 1.6x3.2 smd: +(0,2.4) -(0,-2.4)
  silkscreen extent -3.5,-3.9 3.5,4.2, body extent -3.3,-3.3 3.3,3.3, height 7.7
"SO-8_M FET" [mm] "8-Pin Plastic Small Outline Integrated Circuit 1.27 mm Pitch, IPC Low Density"
  oval 2.5x0.7 smd: D(2.45,1.905) D(2.45,-0.635) D(2.45,0.635) D(2.45,-1.905) G(-2.45,-1.905) S(-2.45,1.905) S(-2.45,-0.635) S(-2.45,0.635)
  silkscreen extent -2.58,-2.5 0.8,2.93, body extent -2,-2.5 2,2.5, height 1.75
SOD-123 [mm]
  rect 0.91x1.22 smd: A(1.638,0) K(-1.638,0)
  silkscreen extent -2.18,-0.9 1.42,0.9, body extent -1.48,-0.96 1.48,0.96, height 1.35
"SOT-23 FET" [mm]
  rect 0.9x0.8 smd: D(1,0) G(-1,0.95) S(-1,-0.95)
  silkscreen extent 0.1,-1.5 0.7,1.5, body extent -0.7,-1.5 0.7,1.5, height 0.97
"T-1 3/4" [mil]
  round 60 hole 35: A(-50,0)
  rect 60x60 hole 35: K(50,0)
  silkscreen extent -116,-116 98,116, body extent -116,-116 99,116, height 354
TO-263AB/D2PAK [mm]
  rect 9.5x10 smd: D(0,10)
  rect 1.7x4.2 smd: G(-2.54,0) S(2.54,0)
  silkscreen extent -5.4,2.5 5.4,14.1, body extent -5.4,-1 5.4,14.1, height 4.83
TPS543X [mil] "Thermally Enhanced SO8"
  rect 80x26 smd: 1(-110,75) 2(-110,25) 3(-110,-25) 4(-110,-75) 5(110,-75) 6(110,-25) 7(110,25) 8(110,75)
  rect 50x60 hole 12.99: PAD(-20,-25) PAD(-20,25) PAD(20,-25) PAD(20,25)
  rect 98x118 smd: PAD(0,0)
  silkscreen extent -107,-98 51,113, body extent -79,-98 79,98, height 69
"WAGO 734-132" [mm] "3.5mm 10 A Protected Header"
  oct 2.8x2.8 hole 1.4: 1(0,0)
  round 2.8 hole 1.4: 2(3.5,0)
  silkscreen extent -2.8,-4.35 6.6,4.15, body extent -3.25,-4.35 6.6,9.1, height 22.4
"WAGO 739-302" [mm] "3.5mm 6 A"
  oct 2.8x2.8 hole 1.1: 1(0,0)
  round 2.8 hole 1.1: 2(3.5,0)
  silkscreen extent -1.75,-5.7 6.75,7.7, body extent -1.75,-5.7 6.8,7.7, height 12.3
"WAGO 745-83X" [mm] "1 Poles of the 745-83X"
  rect 3.048x3.048 / inner rect 3.6x3.6 / far side rect 3.6x3.6 hole 1.8: 1(7.5,12.5) 1(7.5,0)
  silkscreen extent 3.4,-8.6 10.9,17.8, body extent 3.4,-8.6 12.4,20.5, height 23
"WAGO 745-83X Red" [mm] "1 Poles of the 745-83X"
  rect 3.048x3.048 / inner rect 3.6x3.6 / far side rect 3.6x3.6 hole 1.8: 1(7.5,12.5) 1(7.5,0)
  silkscreen extent 3.4,-8.6 10.9,17.8, body extent 3.4,-8.6 12.4,20.5, height 23
"WAGO 745-85X" [mm] "1 Pole of 745-85X"
  rect 3.048x3.048 / inner rect 4.4x4.4 / far side rect 4.4x4.4 hole 2.2: 1(10,15) 1(10,0) 1(14,15) 1(14,0)
  silkscreen extent 7,-10 17,19.6, body extent 7,-9.7 18.5,23.7, height 27
"WAGO 745-85X RED" [mm] "1 Pole of 745-85X"
  rect 3.048x3.048 / inner rect 4.4x4.4 / far side rect 4.4x4.4 hole 2.2: 1(10,15) 1(10,0) 1(14,15) 1(14,0)
  silkscreen extent 7,-10 17,19.6, body extent 7,-9.7 18.5,23.7, height 27
"WAGO 745-300" [mil] "745-83X End Plate"
  silkscreen extent 134,-339 197,669, body extent 134,-339 197,669, height 906
"WAGO 745-500" [mil] "745-85X End Plate"
  silkscreen extent 0,-394 0,748, body extent 0,-382 67,925, height 1055
"Wurth 7461098" [mil] "M6 Press Fit Shank"
  round 85 hole 57.09: PAD(-200,-200) PAD(-200,-100) PAD(-200,0) PAD(-200,100) PAD(-200,200) PAD(-100,-200) PAD(-100,-100) PAD(-100,0) PAD(-100,100) PAD(-100,200) PAD(0,-200) PAD(0,-100) PAD(0,0) PAD(0,100) PAD(0,200) PAD(100,-200) PAD(100,-100) PAD(100,0) PAD(100,100) PAD(100,200) PAD(200,-200) PAD(200,-100) PAD(200,0) PAD(200,100) PAD(200,200)
  silkscreen extent -354,-354 354,354, body extent -256,-256 256,256, height 610
"WURTH WE-HC 744314X" [mm] "SMT Power Inductors"
  rect 2.2x2.7 smd: 1(0,2.55) 2(0,-2.55)
  silkscreen extent -3.75,-3.75 3.75,3.75, body extent -3.45,-3.5 3.45,3.5, height 4.8

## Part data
C1 C2: library part "4.7uF 0805 25V X5R", "CERAMIC 4.7uF 25V X5R 0805"
C3 C5 C19: library part "0.01 uF 0603 50V"
C4 C6 C11 C12 C14 C15 C17 C20: "Capacitor"
C7 C8 C9 C10 C13 C16: library part "22uF 1210 25V X5R", "Capacitor"
C18: library part "330µF 6.3V CAN-SMT", "330µF 6.3V ELECT CAN-SMT"
C21 C22: library part "100µF 35V CAN-SMT", "100µF 35V CAN-SMT"
CB1 CB2 CB3 CB4 CB5 CB6 CB19 CB20 CB21 CB22 CB23 CB24: library part "KeyElco 3557-2", "Standard Automotive Blade Fuse Clips & Holder - Edge"
CB7 CB8 CB9 CB10 CB11 CB12 CB13 CB14: library part "KeyElco 3555-2", "\"MAXI\" Automotive Fuse Clip and Holder"
CB15 CB18: library part "Fuse SSQ 15", "FUSE 12A 125V 6125 FAST SSQ"
CB16: library part MF-SM200-2, "PTC 2A /  4A SMT"
CB17: library part MF-MSMF200-2, "PTC 1.1A /  2.2A SMT"
CB25: library part 2920L300/15DR, "PTC 3A /  5A SMT2920"
D1 D2 D3 D4 D5 D6 D7 D8 D9 D10 D18 D19 D20 D21 D22 D23 D24 D25 D26 D27: library part LTST-S220KRKT, "Red 0805 Side Fire 2.0V 20mA 54mCd"
D11 D14 D17: library part LTL-10233W, "T-1 3/4 Green"
D12 D13 D15: "3A Schottky Diode"
D16 D28: library part MMSZ5242BT1G_1, "12V 500mW Zener"
D30: library part SMCJ26A
J1 J4 J6 J8 J29 J31 J33 J35: library part "Wago 745-85X Grey", "Wago 745-85X Grey"
J2 J36: library part "Wago 745-500", "Wago 745-85X End Plate"
J3 J5 J7 J9 J28 J30 J32 J34: library part "Wago 745-85X Blue", "Wago 745-85X Blue"
J10 J49: library part "Wago 745-300", "Wago 745-83X End Plate"
J11 J13 J15 J17 J19 J21 J38 J40 J42 J44 J46 J48: library part "Wago 745-83X Grey", "Wago 745-83X Grey"
J12 J14 J16 J18 J20 J22 J37 J39 J41 J43 J45 J47: library part "Wago 745-83X Blue", "Wago 745-83X Blue"
J23 J27: library part "Wurth M6 PressFit Shank"
J24 J26: library part "WAGO 734-132", "3.5mm Header Protected against Mismating"
J25: "4 position, vertical locking connector with screw flanges, 3.5mm spacing"
L1: library part "WE-HC 4.7-6", "4.7 µH 6 A 20% SMD"
L2: library part MSS1038-183ML_
L3: library part "WE-HC 6.5-6", "6.5 µH 6 A 20% SMD"
L4 L5: library part BRL3225T1R0M, "1uH 1210 2.4A"
Q1 Q2 Q3 Q4 Q5 Q6 Q7 Q8 Q9 Q10 Q14 Q15 Q16 Q17 Q18 Q19 Q20 Q21 Q22 Q23: library part BSS84LT1, "P-Channel MOSFET, -50V, 130mA, 5 Ohm"
Q11: "N-CH 30V 8SOIC"
Q12: library part FDB8441, "N-Channel Powertrench MOSFET, 40V, 80A, 2.5mOhm"
Q13: "N-CH 40V SO8 12.8A"
R32 R46: library part "25 milliohm RL3720 2% 1W", "25 milliohm RL3720 2% 1W"
R82 R83 R84 R85 R86 R87 R88 R89 R90 R91 R92 R93 R94 R95 R96 R97 R98 R99 R100 R101: library part "100k ohm 0603 1%", "100k ohm 0603 1%"
U1: library part TPS5431, "3-A, WIDE INPUT RANGE, STEP-DOWN SWIFT CONVERTER"
U2: "SEPIC Controller"
U3: "Low Side N Switcher Controller - Boost, Flyback, SEPIC"

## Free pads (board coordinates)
  round 225 hole 200 paste-1000: "Mounting Hole"(4763.78,4527.56) "Mounting Hole"(4763.78,6889.76) "Mounting Hole"(4763.78,9251.97) "Mounting Hole"(11535.43,6889.76) "Mounting Hole"(12204.72,5019.69) "Mounting Hole"(12204.72,8759.84)

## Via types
v1: diameter 40, hole 20, Top Layer to Bottom Layer, 47 vias
v2: diameter 60, hole 35, Top Layer to Bottom Layer, 32 vias
v3: diameter 70, hole 35, Top Layer to Bottom Layer, 4 vias
v4: diameter 50, hole 27.99, Top Layer to Bottom Layer, 4 vias

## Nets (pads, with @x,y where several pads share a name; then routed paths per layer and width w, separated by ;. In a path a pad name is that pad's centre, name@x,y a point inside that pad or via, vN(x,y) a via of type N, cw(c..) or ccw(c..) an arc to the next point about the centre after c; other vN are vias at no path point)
5V_OUT: C15.2 C18.+ D17.A J26.2 L2.2 R43.2 | length 2700
  Top Layer w15: R43.2@10755.91,6972.44 10757.87,6972.44 C15.2@10811.02,6972.44
  Top Layer w30: C15.2@10818.9,6972.44 10877.95,6972.44 10944.88,7039.37 L2.2@11070.87,7039.37
  Top Layer w50: L2.2@11070.87,7035.43 11070.87,7037.4 L2.2@11070.87,7039.37 ; C18.+@11104.33,7224.41 11358.27,7224.41 11535.43,7401.57 11948.82,7401.57 12185.04,7637.8 12273.62,7637.8 12362.2,7726.38 12362.2,7913.39 12318.9,7956.69 J26.2@12246.06,7956.69
  Top Layer w75: L2.2@11086.61,7047.24 C18.+@11086.61,7212.6
  Bottom Layer w12: D17.A@12204.72,8345.28 12250,8300 12250,8110 12246.06,8106.06 J26.2@12246.06,7956.69
12_VIN: C7.2 C10.2 CB15.1 L1.2 R34.2 | length 1087.4
  Top Layer w12: v1(10108.27,6391.73) R34.2@10108.27,6437.01
  Bottom Layer w12: v1(9133.86,6555.12) 9297.24,6391.73 v1(10108.27,6391.73)
12V_OUT: C22.+ D11.A J24.2 L5.2 | length 2667.6
  Top Layer w35: C22.+@10505,6625 10512.24,6632.24 10590.55,6710.55 L5.2@10590.55,6779.53
  Top Layer w50: C22.+@10512.76,6617.24 10629.18,6500.82 v2@10629.18,6338.58 ; D11.A@12204.72,6014.57 12253.15,6014.57 12283.46,5984.25 J24.2@12283.46,5633.86
  Bottom Layer w50: v2(10629.92,6338.58) 10669.29,6299.21 11920.08,6299.21 D11.A@12204.72,6014.57
24_VIN: C13.2 C16.2 CB18.1 L3.2 R47.1 | length 1518.8
  Top Layer w12: v1(10108.27,7179.13) R47.1@10108.27,7224.41
  Bottom Layer w12: v1(9055.12,7431.1) 9104.33,7480.31 10019.68,7480.31 10039.37,7460.63 10039.37,7362.2 9940.94,7263.78 9940.94,7228.35 9990.16,7179.13 v1(10108.27,7179.13)
24V_OUT: C21.+ D14.A D30.K J25.1 J25.3 L4.2 | length 4156.3
  Top Layer w15: D14.A@12204.72,7490.94 12421.26,7274.41 12421.26,6673.23 J25.1@12293.31,6545.28
  Top Layer w35: L4.2@10472.44,7023.62 10472.44,7035.43 10472.44,7142.44 10499.29,7169.29 C21.+@10551.18,7169.29
  Top Layer w50: C21.+@10554.19,7154.47 10560.1,7160.37 10742.24,7342.52 v4(11200.79,7342.52) ; v4(11387.8,7155.51) 11456.69,7086.61 11681.1,7086.61 11807.09,6960.63 11807.09,6759.84 11881.89,6685.04 11881.89,6548.23 D30.K@11996.06,6434.06 12075.79,6434.06 12102.36,6460.63 12102.36,6637.8 12145.66,6681.09 12214.57,6681.09 ; J25.1@12293.31,6545.28 12214.57,6624.02 12214.57,6681.09 ; J25.3@12293.31,6820.87 12214.57,6742.13 12214.57,6681.09
  Bottom Layer w50: v4(11200.79,7342.52) v4(11387.8,7155.51)
GND: J1.1 J4.1 J6.1 J8.1 J11.1 J13.1 J15.1 J17.1 J19.1 J21.1 J27.PAD J29.1 J31.1 J33.1 J35.1 J38.1 J40.1 J42.1 J44.1 J46.1 J48.1 Q12.D
  other v2: 8425.2,7253.94 8582.68,7253.94 8740.16,7253.94 8503.94,7312.99 8661.42,7312.99
HIGHCURRENTOUT_1_1: CB8.2 J3.1 R82.2 | length 47.2
  Top Layer w12: R82.2@5385.83,6000 5433.07,6000
HIGHCURRENTOUT_1_2: CB13.2 J34.1 R86.2 | length 47.2
  Top Layer w12: 7992.13,7779.53 R86.2@8039.37,7779.53
HIGHCURRENTOUT_2_1: CB10.2 J5.1 R83.2 | length 47.2
  Top Layer w12: R83.2@6173.23,6000 6220.47,6000
HIGHCURRENTOUT_2_2: CB11.2 J32.1 R87.2 | length 47.2
  Top Layer w12: 7204.72,7779.53 R87.2@7251.97,7779.53
HIGHCURRENTOUT_3_1: CB12.2 J7.1 R84.2 | length 47.2
  Top Layer w12: R84.2@6960.63,6000 7007.87,6000
HIGHCURRENTOUT_3_2: CB9.2 J30.1 R88.2 | length 47.2
  Top Layer w12: 6417.32,7779.53 R88.2@6464.57,7779.53
HIGHCURRENTOUT_4_1: CB14.2 J9.1 R85.2 | length 47.2
  Top Layer w12: R85.2@7748.03,6000 7795.28,6000
HIGHCURRENTOUT_4_2: CB7.2 J28.1 R89.2 | length 47.2
  Top Layer w12: 5629.92,7779.53 R89.2@5677.17,7779.53
LOWCURRENTOUT_1_1: CB1.2 J12.1 R96.2 | length 49.2
  Top Layer w12: 9035.43,5728.35 R96.2@9035.43,5777.56
LOWCURRENTOUT_1_2: CB24.2 J47.1 R90.2 | length 49.2
  Top Layer w12: R90.2@11251.97,8001.97 11251.97,8051.18
LOWCURRENTOUT_2_1: CB2.2 J14.1 R97.2 | length 49.2
  Top Layer w12: 9625.98,5728.35 R97.2@9625.98,5777.56
LOWCURRENTOUT_2_2: CB23.2 J45.1 R91.2 | length 98.4
  Top Layer w12: R91.2@10661.42,8001.97 R91.2@10661.42,8005.91 ; 10661.42,8051.18 R91.2@10661.42,8005.91 ; 10661.42,8055.12 R91.2@10661.42,8005.91
LOWCURRENTOUT_3_1: CB3.2 J16.1 R98.2 | length 49.2
  Top Layer w12: 10216.54,5728.35 R98.2@10216.54,5777.56
LOWCURRENTOUT_3_2: CB22.2 J43.1 R92.2 | length 49.2
  Top Layer w12: R92.2@10070.87,8001.97 10070.87,8051.18
LOWCURRENTOUT_4_1: CB4.2 J18.1 R99.2 | length 49.2
  Top Layer w12: 10807.09,5728.35 R99.2@10807.09,5777.56
LOWCURRENTOUT_4_2: CB21.2 J41.1 R93.2 | length 49.2
  Top Layer w12: R93.2@9480.32,8001.97 9480.32,8051.18
LOWCURRENTOUT_5_1: CB5.2 J20.1 R100.2 | length 49.2
  Top Layer w12: 11397.64,5728.35 R100.2@11397.64,5777.56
